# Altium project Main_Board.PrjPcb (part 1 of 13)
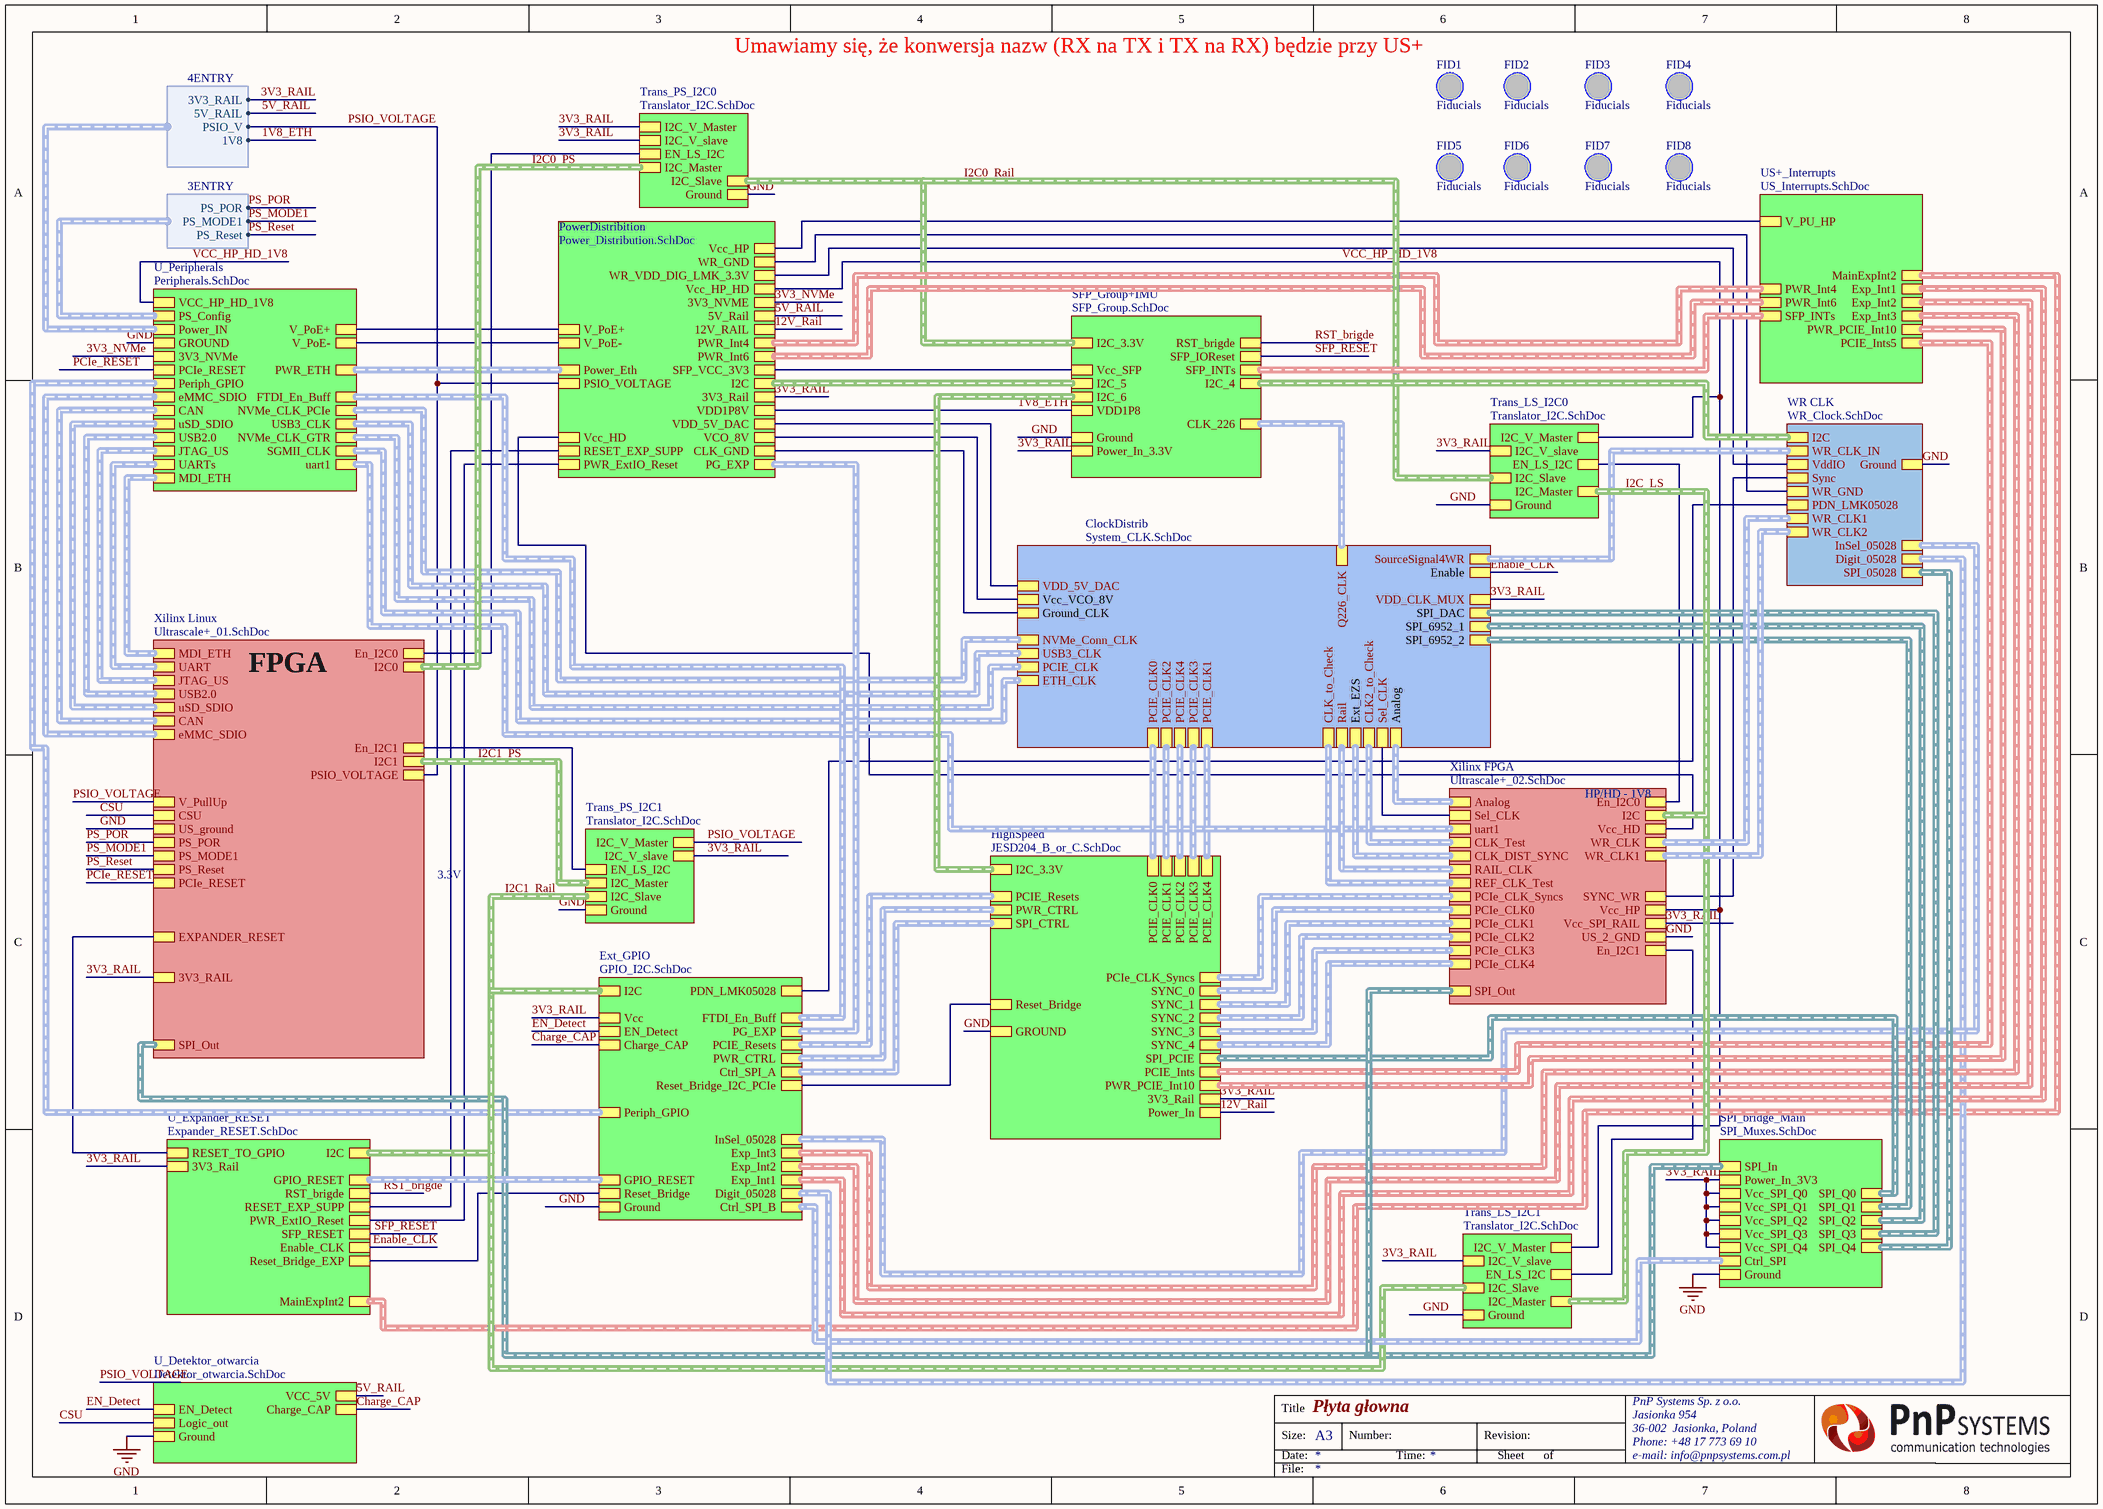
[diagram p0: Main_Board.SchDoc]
Address10: Jasionka 954; Address20: 36-002  Jasionka, Poland; Address30: Phone: +48 17 773 69 10; Address40: e-mail: info@pnpsystems.com.pl; CompanyName1: PnP Systems Sp. z o.o.
70 sheets, 2644 parts. Net scope: hierarchical (ports join the sheet entries above them; power ports are global).
Board file: MainBoardPCB.PcbDoc
Sheets:
  Main_Board.SchDoc
    Xilinx Linux = Ultrascale+_01.SchDoc
      PS_Config = PS_Config.SchDoc
      U_LED_US_1 = LED_US_1.SchDoc
    WR CLK = WR_Clock.SchDoc
    ClockDistrib = System_CLK.SchDoc
      DAC = DAC.SchDoc
      CLK_MUX = CLK_Mux.SchDoc
      LTC6952_1 = LTC6952_1.SchDoc
      LTC6952_0 = LTC6952.SchDoc
    Xilinx FPGA = Ultrascale+_02.SchDoc
    HighSpeed = JESD204_B_or_C.SchDoc
      PCIE0 = PCIe.SchDoc
      PCIE1 = PCIe.SchDoc
      PCIE2 = PCIe.SchDoc
      PCIE3 = PCIe.SchDoc
      PCIE4 = PCIe.SchDoc
      Bank 224 = Bank224.SchDoc
      Bank 225 = Bank225.SchDoc
      Bank 223 = Bank223.SchDoc
      I2C_Bridge_PCIE = I2C_Bridge.SchDoc
      SPI_bridge_PCIe = SPI_Muxes.SchDoc
      Power4HighSpeed = Power4HiSpeed.SchDoc
        U_Pomiar_pradu_napiecia_PCIe0 = Pomiar_pradu_napiecia.SchDoc
        U_Pomiar_pradu_napiecia_PCIe1 = Pomiar_pradu_napiecia.SchDoc
        U_Pomiar_pradu_napiecia_PCIe2 = Pomiar_pradu_napiecia.SchDoc
        U_Pomiar_pradu_napiecia_PCIe3 = Pomiar_pradu_napiecia.SchDoc
        U_Pomiar_pradu_napiecia_PCIe4 = Pomiar_pradu_napiecia.SchDoc
    PowerDistribition = Power_Distribution.SchDoc
      PowerSelector = Power_Switch.SchDoc
      HiCurrent = Power_Hi_Curr.SchDoc
        U_HI_Curr_ADP1850_1 = HI_Curr_ADP1850.SchDoc
        U_HI_Curr_ADP1850_3 = Power_ADP1850_Dual.SchDoc
        U_Power_ADP1850_Dual_2 = Power_ADP1850_Dual_1.SchDoc
        U_Pomiar_pradu_napiecia_3 = Pomiar_pradu_napiecia.SchDoc
        U_Pomiar_pradu_napiecia_4 = Pomiar_pradu_napiecia.SchDoc
        U_Pomiar_pradu_napiecia_5 = Pomiar_pradu_napiecia.SchDoc
        U_Pomiar_pradu_napiecia_6 = Pomiar_pradu_napiecia.SchDoc
        U_Pomiar_napiecia_high_curr = Pomiar_napiecia_high_curr.SchDoc
      LowCurr = Power_Low_Curr.SchDoc
      Zasilanie CLK = Zasilanie_CLKDistribution.SchDoc
        U_ADP1741_3 = ADP1741_3.6V_3.3V@2A.SchDoc
        5to3V3_1 = 5V_to_3V3.SchDoc
        5to3V3_2 = 5V_to_3V3.SchDoc
        U_LT3042_12V_5V_LNLDO = LT3042_12V_5V_LNLDO.SchDoc
        U_TPS7A88_5V_Dual_3 = TPS7A88_5V_Dual_3.3V_3.3V.SchDoc
        I2C_Expander_PWR_CLK = I2C_Expander.SchDoc
      Ram_Power = RAM_Power.SchDoc
      XilinxPower = XilinxPower.SchDoc
        U_FPGA_Decoupling = FPGA_Decoupling.SchDoc
      Ram = RAM.SchDoc
      GND = Ground.SchDoc
      U_Power_Ethernet = Power_Ethernet.SchDoc
      I2C_Expander_PWR_Dist = I2C_Expander.SchDoc
      U_Pomiar_pradu_napiecia_1 = Pomiar_pradu_napiecia.SchDoc
      U_Pomiar_pradu_napiecia_2 = Pomiar_pradu_napiecia.SchDoc
      U_Power_48_20V@3A = Power_48_20V@3A.SchDoc
      U_UM78M_12_8V = UM78M_12_8V.SchDoc
      U_TPS7A88_3V3_1V8_0V9V@2x1A = TPS7A88_3V3_1V8_0V9V@2x1A.SchDoc
      U_ADP1741_3V3_0V85 = ADP1741_3V3_0V85.SchDoc
      U_ST1L08_5V_0V6 = ST1L08_5V_0V6.SchDoc
      U_Power_LED = Power_LED.SchDoc
    Trans_LS_I2C0 = Translator_I2C.SchDoc
    Ext_GPIO = GPIO_I2C.SchDoc
      I2C_Bridge_GPIO = I2C_Bridge.SchDoc
      Ext_GPIO_Bank0 = Ext_GPIO_Bank0.SchDoc
        I2C_Expander_00 = I2C_Expander.SchDoc
        I2C_Expander_01 = I2C_Expander.SchDoc
        I2C_Expander_02 = I2C_Expander.SchDoc
      Ext_GPIO_Bank1 = Ext_GPIO_Bank1.SchDoc
        I2C_Expander_10 = I2C_Expander.SchDoc
        I2C_Expander_11 = I2C_Expander.SchDoc
        I2C_Expander_12 = I2C_Expander.SchDoc
      Ext_GPIO_Bank2 = Ext_GPIO_Bank2.SchDoc
    SFP_Group+IMU = SFP_Group.SchDoc
      SFP0 = SFP.SchDoc
      SFP1 = SFP1.SchDoc
      SFP2 = SFP2.SchDoc
      SFP3 = SFP3.SchDoc
      I2C_Bridge_SFP = I2C_Bridge.SchDoc
      Bank 226 = bank226.SchDoc
      IMU = IMU.SchDoc
      I2C_Expander_SFP = I2C_Expander.SchDoc
    Trans_PS_I2C0 = Translator_I2C.SchDoc
    Trans_PS_I2C1 = Translator_I2C.SchDoc
    SPI_bridge_Main = SPI_Muxes.SchDoc
    Trans_LS_I2C1 = Translator_I2C.SchDoc
    U_Detektor_otwarcia = Detektor_otwarcia.SchDoc
    U_Peripherals = Peripherals.SchDoc
      Gigabit Eth = RJ45.SchDoc
      NVMe = Sata.SchDoc
      µSD = uSD.SchDoc
      Debug = FTDI.SchDoc
        5V_to_3V3_for_FTDI = 5V_to_3V3.SchDoc
      USB3.0 = USB3.SchDoc
      U_CAN = CAN.SchDoc
      Flash_Memory = eMMC.SchDoc
      GTR = GTR.SchDoc
    U_Expander_RESET = Expander_RESET.SchDoc
      I2C_Expander_Main_Rst = I2C_Expander.SchDoc
    US+_Interrupts = US_Interrupts.SchDoc

## Sheet Main_Board.SchDoc: Płyta głowna
size A3; Organization: Altium Limited; Address1: L3, 12a Rodborough Rd; Address2: Frenchs Forest; Address3: NSW; Address4: Australia 2086

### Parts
FID1  Fiducials  [Fiducials]
FID2  Fiducials  [Fiducials]
FID3  Fiducials  [Fiducials]
FID4  Fiducials  [Fiducials]
FID5  Fiducials  [Fiducials]
FID6  Fiducials  [Fiducials]
FID7  Fiducials  [Fiducials]
FID8  Fiducials  [Fiducials]

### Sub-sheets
ClockDistrib = System_CLK.SchDoc: SPI_6952_1 (harness SPI_H), Ground_CLK, Ext_EZS (harness Diff_1Pair), Enable, Analog (harness Analog), Vcc_VCO_8V, SPI_6952_2 (harness SPI_H), SPI_DAC (harness SPI_H), Q226_CLK (harness Diff_1Pair), SourceSignal4WR (harness Diff_1Pair), Rail (harness Diff_1Pair), CLK_to_Check (harness Diff_1Pair), ETH_CLK (harness Diff_1Pair), USB3_CLK (harness Diff_1Pair), PCIE_CLK (harness Diff_1Pair), Sel_CLK, CLK2_to_Check (harness Diff_1Pair), NVMe_Conn_CLK (harness Diff_1Pair), VDD_5V_DAC, VDD_CLK_MUX, PCIE_CLK0 (harness Diff_1Pair), PCIE_CLK2 (harness Diff_1Pair), PCIE_CLK4 (harness Diff_1Pair), PCIE_CLK3 (harness Diff_1Pair), PCIE_CLK1 (harness Diff_1Pair)
Ext_GPIO = GPIO_I2C.SchDoc: Ctrl_SPI_B (harness Ctrl_SPI_PCIE), Ctrl_SPI_A (harness Ctrl_SPI_PCIE), Ground, Vcc, I2C (harness I2C), Digit_05028 (harness 05028_Digit), GPIO_RESET (harness Exp_Reset3), Reset_Bridge, PG_EXP (harness 7_PG), PDN_LMK05028, EN_Detect, Charge_CAP, Exp_Int1 (harness Exp_Int), PCIE_Resets (harness PCIe_Resets), PWR_CTRL (harness Ctrl_Pwr4HiSpeed), Periph_GPIO (harness Periph_GPIO), Exp_Int2 (harness Exp_Int), Exp_Int3 (harness Exp_Int), InSel_05028 (harness InSel_05028), FTDI_En_Buff (harness FTDI_En_Buff), Reset_Bridge_I2C_PCIe
HighSpeed = JESD204_B_or_C.SchDoc: PCIE_Resets (harness PCIe_Resets), SPI_PCIE (harness SPI_H), Power_In, SPI_CTRL (harness Ctrl_SPI_PCIE), PWR_CTRL (harness Ctrl_Pwr4HiSpeed), I2C_3.3V (harness I2C), Reset_Bridge, 3V3_Rail, PWR_PCIE_Int10 (harness PWR_PCIE_Int10), GROUND, PCIE_Ints (harness PCIe_Ints), PCIe_CLK_Syncs (harness PCIe_CLK_Syncs), SYNC_4 (harness Diff_3Diff_Pcie), SYNC_3 (harness Diff_3Diff_Pcie), SYNC_2 (harness Diff_3Diff_Pcie), SYNC_1 (harness Diff_3Diff_Pcie), SYNC_0 (harness Diff_3Diff_Pcie), PCIE_CLK4 (harness Diff_1Pair), PCIE_CLK0 (harness Diff_1Pair), PCIE_CLK3 (harness Diff_1Pair), PCIE_CLK1 (harness Diff_1Pair), PCIE_CLK2 (harness Diff_1Pair)
PowerDistribition = Power_Distribution.SchDoc: Power_Eth (harness Power_ETH), V_PoE-, V_PoE+, SFP_VCC_3V3, 3V3_Rail, I2C (harness I2C), VDD1P8V, 12V_RAIL, PWR_Int4 (harness PWR_Int4), PWR_ExtIO_Reset, 5V_Rail, PWR_Int6 (harness PWR_Interrupt), WR_VDD_DIG_LMK_3.3V, PSIO_VOLTAGE, VCO_8V, 3V3_NVME, VDD_5V_DAC, Vcc_HP_HD, WR_GND, CLK_GND, RESET_EXP_SUPP, PG_EXP (harness 7_PG), Vcc_HP, Vcc_HD
SFP_Group+IMU = SFP_Group.SchDoc: I2C_3.3V (harness I2C), RST_brigde, Ground, Vcc_SFP, SFP_INTs (harness SFP_INTs), I2C_5 (harness I2C), Power_In_3.3V, VDD1P8, SFP_IOReset, CLK_226 (harness Diff_1Pair), I2C_6 (harness I2C), I2C_4 (harness I2C)
SPI_bridge_Main = SPI_Muxes.SchDoc: SPI_Q0 (harness SPI_H), SPI_Q1 (harness SPI_H), SPI_Q2 (harness SPI_H), SPI_Q3 (harness SPI_H), SPI_Q4 (harness SPI_H), SPI_In (harness SPI_H), Power_In_3V3, Ctrl_SPI (harness Ctrl_SPI_PCIE), Vcc_SPI_Q4, Vcc_SPI_Q3, Vcc_SPI_Q2, Vcc_SPI_Q1, Vcc_SPI_Q0, Ground
Trans_LS_I2C0 = Translator_I2C.SchDoc: Ground, EN_LS_I2C, I2C_Slave (harness I2C), I2C_Master (harness I2C), I2C_V_slave, I2C_V_Master
Trans_LS_I2C1 = Translator_I2C.SchDoc: Ground, EN_LS_I2C, I2C_Slave (harness I2C), I2C_Master (harness I2C), I2C_V_slave, I2C_V_Master
Trans_PS_I2C0 = Translator_I2C.SchDoc: Ground, EN_LS_I2C, I2C_Slave (harness I2C), I2C_Master (harness I2C), I2C_V_slave, I2C_V_Master
Trans_PS_I2C1 = Translator_I2C.SchDoc: Ground, EN_LS_I2C, I2C_Slave (harness I2C), I2C_Master (harness I2C), I2C_V_slave, I2C_V_Master
U_Detektor_otwarcia = Detektor_otwarcia.SchDoc: EN_Detect, Logic_out, Ground, VCC_5V, Charge_CAP
U_Expander_RESET = Expander_RESET.SchDoc: 3V3_Rail, RESET_TO_GPIO, GPIO_RESET (harness Exp_Reset3), RESET_EXP_SUPP, PWR_ExtIO_Reset, SFP_RESET, MainExpInt2 (harness MainExpInt2), RST_brigde, Enable_CLK, Reset_Bridge_EXP, I2C (harness I2C)
U_Peripherals = Peripherals.SchDoc: 3V3_NVMe, GROUND, V_PoE+, V_PoE-, PS_Config (harness 3ENTRY), Periph_GPIO (harness Periph_GPIO), Power_IN (harness 4ENTRY), PWR_ETH (harness Power_ETH), uart1 (harness uart), UARTs (harness 2Uarts), USB2.0 (harness USB_H), MDI_ETH (harness MDI_ETH), CAN (harness CAN), uSD_SDIO (harness SDIO_H), eMMC_SDIO (harness SDIO_H), NVMe_CLK_GTR (harness Diff_1Pair), USB3_CLK (harness Diff_1Pair), SGMII_CLK (harness Diff_1Pair), JTAG_US (harness JTAG), NVMe_CLK_PCIe (harness Diff_1Pair), VCC_HP_HD_1V8, FTDI_En_Buff (harness FTDI_En_Buff), PCIe_RESET
US+_Interrupts = US_Interrupts.SchDoc: V_PU_HP, MainExpInt2 (harness MainExpInt2), PCIE_Ints5 (harness PCIe_Ints5), PWR_Int4 (harness PWR_Int4), PWR_Int6 (harness PWR_Interrupt), SFP_INTs (harness SFP_INTs), Exp_Int1 (harness Exp_Int), PWR_PCIE_Int10 (harness PWR_PCIE_Int10), Exp_Int2 (harness Exp_Int), Exp_Int3 (harness Exp_Int)
WR CLK = WR_Clock.SchDoc: WR_CLK1 (harness Diff_1Pair), WR_CLK2 (harness Diff_1Pair), Sync, VddIO, WR_CLK_IN (harness Diff_1Pair), SPI_05028 (harness SPI_H), Ground, Digit_05028 (harness 05028_Digit), I2C (harness I2C), WR_GND, PDN_LMK05028, InSel_05028 (harness InSel_05028)
Xilinx FPGA = Ultrascale+_02.SchDoc: I2C (harness I2C), SPI_Out (harness SPI_H), uart1 (harness uart), En_I2C0, WR_CLK (harness Diff_1Pair), REF_CLK_Test (harness Diff_1Pair), RAIL_CLK (harness Diff_1Pair), Analog (harness Analog), CLK_DIST_SYNC (harness Diff_1Pair), WR_CLK1 (harness Diff_1Pair), Vcc_HP, US_2_GND, Vcc_SPI_RAIL, En_I2C1, Sel_CLK, SYNC_WR, CLK_Test (harness Diff_1Pair), PCIe_CLK_Syncs (harness PCIe_CLK_Syncs), Vcc_HD, PCIe_CLK2 (harness Diff_3Diff_Pcie), PCIe_CLK4 (harness Diff_3Diff_Pcie), PCIe_CLK1 (harness Diff_3Diff_Pcie), PCIe_CLK3 (harness Diff_3Diff_Pcie), PCIe_CLK0 (harness Diff_3Diff_Pcie)
Xilinx Linux = Ultrascale+_01.SchDoc: I2C0 (harness I2C), SPI_Out (harness SPI_H), I2C1 (harness I2C), En_I2C0, En_I2C1, V_PullUp, US_ground, CSU, PSIO_VOLTAGE, PS_POR, PS_MODE1, PS_Reset, UART (harness 2Uarts), EXPANDER_RESET, MDI_ETH (harness MDI_ETH), USB2.0 (harness USB_H), eMMC_SDIO (harness SDIO_H), CAN (harness CAN), uSD_SDIO (harness SDIO_H), JTAG_US (harness JTAG), PCIe_RESET, 3V3_RAIL  | Parameter 1: FPGA

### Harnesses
4ENTRY: 3V3_RAIL, 5V_RAIL, PSIO_V, 1V8
3ENTRY: PS_POR, PS_MODE1, PS_Reset

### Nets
GND: sheet Xilinx Linux/US_ground, sheet WR CLK/Ground, sheet Xilinx FPGA/US_2_GND, sheet HighSpeed/GROUND, sheet Trans_LS_I2C0/Ground, sheet Ext_GPIO/Ground, sheet SFP_Group+IMU/Ground, sheet Trans_PS_I2C0/Ground, sheet Trans_PS_I2C1/Ground, sheet SPI_bridge_Main/Ground, sheet Trans_LS_I2C1/Ground, sheet U_Detektor_otwarcia/Ground, sheet U_Peripherals/GROUND  [project net B503_Ground]
1V8_ETH: sheet PowerDistribition/VDD1P8V, sheet SFP_Group+IMU/VDD1P8, sheet U_Peripherals/Power_IN.1V8  [project net 1V8@1.5A]
3V3_NVMe: sheet PowerDistribition/3V3_NVME, sheet U_Peripherals/3V3_NVMe
3V3_RAIL: sheet Xilinx Linux/3V3_RAIL, sheet ClockDistrib/VDD_CLK_MUX, sheet Xilinx FPGA/Vcc_SPI_RAIL, sheet HighSpeed/3V3_Rail, sheet PowerDistribition/SFP_VCC_3V3, sheet PowerDistribition/3V3_Rail, sheet Trans_LS_I2C0/I2C_V_slave, sheet Ext_GPIO/Vcc, sheet SFP_Group+IMU/Vcc_SFP, sheet SFP_Group+IMU/Power_In_3.3V, sheet Trans_PS_I2C0/I2C_V_slave, sheet Trans_PS_I2C0/I2C_V_Master, sheet Trans_PS_I2C1/I2C_V_slave, sheet SPI_bridge_Main/Power_In_3V3, sheet SPI_bridge_Main/Vcc_SPI_Q4, sheet SPI_bridge_Main/Vcc_SPI_Q3, sheet SPI_bridge_Main/Vcc_SPI_Q2, sheet SPI_bridge_Main/Vcc_SPI_Q1, sheet SPI_bridge_Main/Vcc_SPI_Q0, sheet Trans_LS_I2C1/I2C_V_slave, sheet U_Expander_RESET/3V3_Rail, sheet U_Peripherals/Power_IN.3V3_RAIL
5V_LN: sheet ClockDistrib/VDD_5V_DAC, sheet PowerDistribition/VDD_5V_DAC
5V_RAIL: sheet PowerDistribition/5V_Rail, sheet U_Detektor_otwarcia/VCC_5V, sheet U_Peripherals/Power_IN.5V_RAIL
12V_Rail: sheet HighSpeed/Power_In, sheet PowerDistribition/12V_RAIL  [project net 12V_LT3042]
AGND: sheet ClockDistrib/Ground_CLK, sheet PowerDistribition/CLK_GND
Charge_CAP: sheet Ext_GPIO/Charge_CAP, sheet U_Detektor_otwarcia/Charge_CAP
CSU: sheet Xilinx Linux/CSU, sheet U_Detektor_otwarcia/Logic_out
D_05028_G0: sheet WR CLK/Sync, sheet Xilinx FPGA/SYNC_WR
EN_Detect: sheet Ext_GPIO/EN_Detect, sheet U_Detektor_otwarcia/EN_Detect
Enable_CLK: sheet ClockDistrib/Enable, sheet U_Expander_RESET/Enable_CLK
EXPANDER_RESET: sheet Xilinx Linux/EXPANDER_RESET, sheet U_Expander_RESET/RESET_TO_GPIO
GPIOa_11.GPIO7: sheet WR CLK/PDN_LMK05028, sheet Ext_GPIO/PDN_LMK05028
GPIOb_02.GPIO0: sheet HighSpeed/Reset_Bridge, sheet Ext_GPIO/Reset_Bridge_I2C_PCIe
Ground: sheet WR CLK/WR_GND, sheet PowerDistribition/WR_GND
MIO_GPIO_2_74: sheet Xilinx Linux/En_I2C1, sheet Trans_PS_I2C1/EN_LS_I2C
MIO_GPIO_2_75: sheet Xilinx Linux/En_I2C0, sheet Trans_PS_I2C0/EN_LS_I2C
PCIe_RESET: sheet Xilinx Linux/PCIe_RESET, sheet U_Peripherals/PCIe_RESET
PGND: sheet PowerDistribition/V_PoE-, sheet U_Peripherals/V_PoE-
PS_MODE1: sheet Xilinx Linux/PS_MODE1, sheet U_Peripherals/PS_Config.PS_MODE1
PS_POR: sheet Xilinx Linux/PS_POR, sheet U_Peripherals/PS_Config.PS_POR
PS_Reset: sheet Xilinx Linux/PS_Reset, sheet U_Peripherals/PS_Config.PS_Reset
PSIO_VOLTAGE: sheet Xilinx Linux/V_PullUp, sheet Xilinx Linux/PSIO_VOLTAGE, sheet PowerDistribition/PSIO_VOLTAGE, sheet Trans_PS_I2C1/I2C_V_Master, sheet U_Peripherals/Power_IN.PSIO_V  [project net ETH_VDDIO]
PWR_ExtIO_nReset: sheet PowerDistribition/PWR_ExtIO_Reset, sheet U_Expander_RESET/PWR_ExtIO_Reset
RST_brigde: sheet SFP_Group+IMU/RST_brigde, sheet U_Expander_RESET/RST_brigde
SetClk_Si53323_2: sheet ClockDistrib/Sel_CLK, sheet Xilinx FPGA/Sel_CLK
SFP_RESET: sheet SFP_Group+IMU/SFP_IOReset, sheet U_Expander_RESET/SFP_RESET  [project net SFP_IO_nReset]
V_PoE+: sheet PowerDistribition/V_PoE+, sheet U_Peripherals/V_PoE+
VCC_HP_HD_1V8: sheet Xilinx FPGA/Vcc_HP, sheet Xilinx FPGA/Vcc_HD, sheet PowerDistribition/Vcc_HP_HD, sheet PowerDistribition/Vcc_HP, sheet PowerDistribition/Vcc_HD, sheet Trans_LS_I2C0/I2C_V_Master, sheet Trans_LS_I2C1/I2C_V_Master, sheet U_Peripherals/VCC_HP_HD_1V8, sheet US+_Interrupts/V_PU_HP  [project net US+_MGTVccAux]
VDD_DIG: sheet WR CLK/VddIO, sheet PowerDistribition/WR_VDD_DIG_LMK_3.3V
NetC713_2: sheet ClockDistrib/Vcc_VCO_8V, sheet PowerDistribition/VCO_8V
NetR754_1: sheet PowerDistribition/RESET_EXP_SUPP, sheet U_Expander_RESET/RESET_EXP_SUPP
NetR918_2: sheet Xilinx FPGA/En_I2C0, sheet Trans_LS_I2C0/EN_LS_I2C
NetR919_2: sheet Xilinx FPGA/En_I2C1, sheet Trans_LS_I2C1/EN_LS_I2C
NetSP12_I2C_Bridge_GPIO_1: sheet Ext_GPIO/Reset_Bridge, sheet U_Expander_RESET/Reset_Bridge_EXP

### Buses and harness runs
harness I2C0_PS = sheet Trans_PS_I2C0/I2C_Master = sheet Xilinx Linux/I2C0
harness I2C0_Rail = sheet SFP_Group+IMU/I2C_3.3V = sheet Trans_LS_I2C0/I2C_Slave = sheet Trans_PS_I2C0/I2C_Slave
harness I2C1_PS = sheet Trans_PS_I2C1/I2C_Master = sheet Xilinx Linux/I2C1
harness I2C1_Rail = sheet Ext_GPIO/I2C = sheet Trans_LS_I2C1/I2C_Slave = sheet Trans_PS_I2C1/I2C_Slave = sheet U_Expander_RESET/I2C
harness I2C_LS = sheet Trans_LS_I2C0/I2C_Master = sheet Trans_LS_I2C1/I2C_Master = sheet Xilinx FPGA/I2C
harness sheet ClockDistrib/Analog = sheet Xilinx FPGA/Analog
harness sheet ClockDistrib/CLK2_to_Check = sheet Xilinx FPGA/CLK_Test
harness sheet ClockDistrib/CLK_to_Check = sheet Xilinx FPGA/REF_CLK_Test
harness sheet ClockDistrib/ETH_CLK = sheet U_Peripherals/SGMII_CLK
harness sheet ClockDistrib/Ext_EZS = sheet Xilinx FPGA/CLK_DIST_SYNC
harness sheet ClockDistrib/NVMe_Conn_CLK = sheet U_Peripherals/NVMe_CLK_PCIe
harness sheet ClockDistrib/PCIE_CLK0 = sheet HighSpeed/PCIE_CLK0
harness sheet ClockDistrib/PCIE_CLK1 = sheet HighSpeed/PCIE_CLK4
harness sheet ClockDistrib/PCIE_CLK2 = sheet HighSpeed/PCIE_CLK1
harness sheet ClockDistrib/PCIE_CLK3 = sheet HighSpeed/PCIE_CLK3
harness sheet ClockDistrib/PCIE_CLK4 = sheet HighSpeed/PCIE_CLK2
harness sheet ClockDistrib/PCIE_CLK = sheet U_Peripherals/NVMe_CLK_GTR
harness sheet ClockDistrib/Q226_CLK = sheet SFP_Group+IMU/CLK_226
harness sheet ClockDistrib/Rail = sheet Xilinx FPGA/RAIL_CLK
harness sheet ClockDistrib/SourceSignal4WR = sheet WR CLK/WR_CLK_IN
harness sheet ClockDistrib/SPI_6952_1 = sheet SPI_bridge_Main/SPI_Q2
harness sheet ClockDistrib/SPI_6952_2 = sheet SPI_bridge_Main/SPI_Q1
harness sheet ClockDistrib/SPI_DAC = sheet SPI_bridge_Main/SPI_Q3
harness sheet ClockDistrib/USB3_CLK = sheet U_Peripherals/USB3_CLK
harness sheet Ext_GPIO/Ctrl_SPI_A = sheet HighSpeed/SPI_CTRL
harness sheet Ext_GPIO/Ctrl_SPI_B = sheet SPI_bridge_Main/Ctrl_SPI
harness sheet Ext_GPIO/Digit_05028 = sheet WR CLK/Digit_05028
harness sheet Ext_GPIO/Exp_Int1 = sheet US+_Interrupts/Exp_Int1
harness sheet Ext_GPIO/Exp_Int2 = sheet US+_Interrupts/Exp_Int2
harness sheet Ext_GPIO/Exp_Int3 = sheet US+_Interrupts/Exp_Int3
harness sheet Ext_GPIO/FTDI_En_Buff = sheet U_Peripherals/FTDI_En_Buff
harness sheet Ext_GPIO/GPIO_RESET = sheet U_Expander_RESET/GPIO_RESET
harness sheet Ext_GPIO/InSel_05028 = sheet WR CLK/InSel_05028
harness sheet Ext_GPIO/PCIE_Resets = sheet HighSpeed/PCIE_Resets
harness sheet Ext_GPIO/Periph_GPIO = sheet U_Peripherals/Periph_GPIO
harness sheet Ext_GPIO/PG_EXP = sheet PowerDistribition/PG_EXP
harness sheet Ext_GPIO/PWR_CTRL = sheet HighSpeed/PWR_CTRL
harness sheet HighSpeed/I2C_3.3V = sheet SFP_Group+IMU/I2C_6
harness sheet HighSpeed/PCIe_CLK_Syncs = sheet Xilinx FPGA/PCIe_CLK_Syncs
harness sheet HighSpeed/PCIE_Ints = sheet US+_Interrupts/PCIE_Ints5
harness sheet HighSpeed/PWR_PCIE_Int10 = sheet US+_Interrupts/PWR_PCIE_Int10
harness sheet HighSpeed/SPI_PCIE = sheet SPI_bridge_Main/SPI_Q0
harness sheet HighSpeed/SYNC_0 = sheet Xilinx FPGA/PCIe_CLK0
harness sheet HighSpeed/SYNC_1 = sheet Xilinx FPGA/PCIe_CLK1
harness sheet HighSpeed/SYNC_2 = sheet Xilinx FPGA/PCIe_CLK2
harness sheet HighSpeed/SYNC_3 = sheet Xilinx FPGA/PCIe_CLK3
harness sheet HighSpeed/SYNC_4 = sheet Xilinx FPGA/PCIe_CLK4
harness sheet PowerDistribition/I2C = sheet SFP_Group+IMU/I2C_5
harness sheet PowerDistribition/Power_Eth = sheet U_Peripherals/PWR_ETH
harness sheet PowerDistribition/PWR_Int4 = sheet US+_Interrupts/PWR_Int4
harness sheet PowerDistribition/PWR_Int6 = sheet US+_Interrupts/PWR_Int6
harness sheet SFP_Group+IMU/I2C_4 = sheet WR CLK/I2C
harness sheet SFP_Group+IMU/SFP_INTs = sheet US+_Interrupts/SFP_INTs
harness sheet SPI_bridge_Main/SPI_In = sheet Xilinx FPGA/SPI_Out = sheet Xilinx Linux/SPI_Out
harness sheet SPI_bridge_Main/SPI_Q4 = sheet WR CLK/SPI_05028
harness sheet U_Expander_RESET/MainExpInt2 = sheet US+_Interrupts/MainExpInt2
harness sheet U_Peripherals/CAN = sheet Xilinx Linux/CAN
harness sheet U_Peripherals/eMMC_SDIO = sheet Xilinx Linux/eMMC_SDIO
harness sheet U_Peripherals/JTAG_US = sheet Xilinx Linux/JTAG_US
harness sheet U_Peripherals/MDI_ETH = sheet Xilinx Linux/MDI_ETH
harness sheet U_Peripherals/uart1 = sheet Xilinx FPGA/uart1
harness sheet U_Peripherals/UARTs = sheet Xilinx Linux/UART
harness sheet U_Peripherals/USB2.0 = sheet Xilinx Linux/USB2.0
harness sheet U_Peripherals/uSD_SDIO = sheet Xilinx Linux/uSD_SDIO
harness sheet WR CLK/WR_CLK1 = sheet Xilinx FPGA/WR_CLK
harness sheet WR CLK/WR_CLK2 = sheet Xilinx FPGA/WR_CLK1

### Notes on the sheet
- Umawiamy się, że konwersja nazw (RX na TX i TX na RX) będzie przy US+
- HP/HD - 1V8
- 3.3V

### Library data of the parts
FID1-FID8 = Fid

## Sheet Ultrascale+_01.SchDoc: Ultrascale+_01
size A3; Organization: Altium Limited; Address1: L3, 12a Rodborough Rd; Address2: Frenchs Forest; Address3: NSW; Address4: Australia 2086
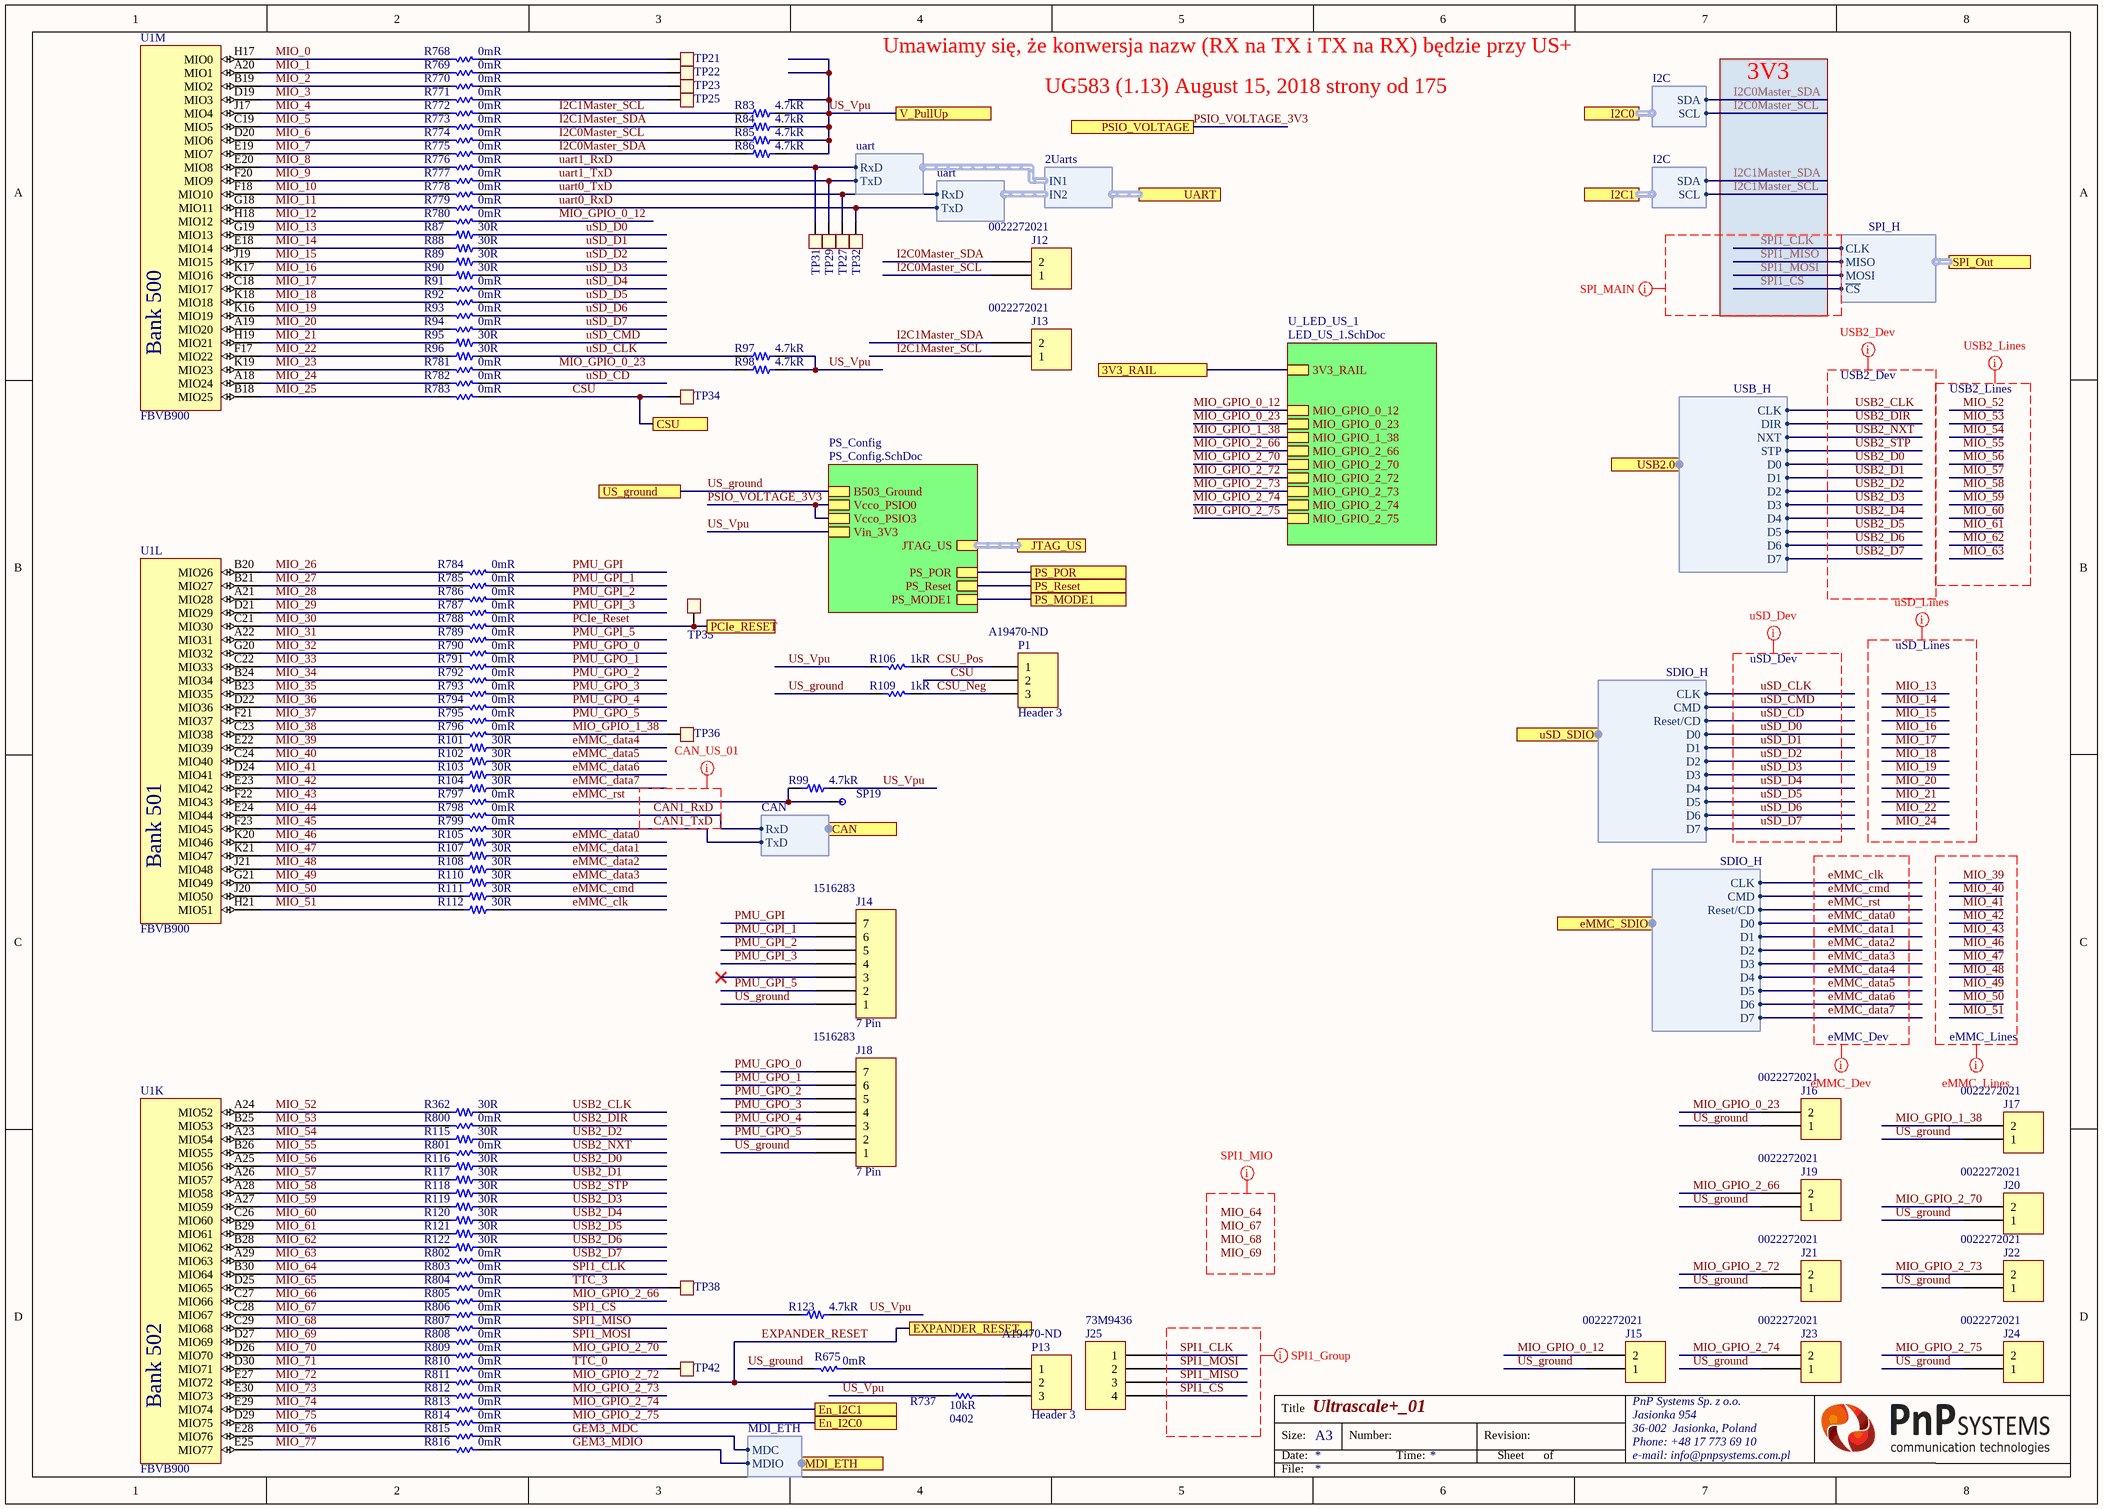
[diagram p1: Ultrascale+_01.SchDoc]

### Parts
J12  Supplier Part Number 1: 0022272021  [MOLEX KK 0022272021]  (hidden comment: MOLEX - 22-27-2021 - WIRE-BOARD CONNECTOR HEADER 2 POSITION, 2.54MM)
J13  Supplier Part Number 1: 0022272021  [MOLEX KK 0022272021]  (hidden comment: MOLEX - 22-27-2021 - WIRE-BOARD CONNECTOR HEADER 2 POSITION, 2.54MM)
J14  7 Pin  Supplier Part Number 1: 1516283  [JST XH B7B-XH-A]
J15  Supplier Part Number 1: 0022272021  [MOLEX KK 0022272021]  (hidden comment: MOLEX - 22-27-2021 - WIRE-BOARD CONNECTOR HEADER 2 POSITION, 2.54MM)
J16  Supplier Part Number 1: 0022272021  [MOLEX KK 0022272021]  (hidden comment: MOLEX - 22-27-2021 - WIRE-BOARD CONNECTOR HEADER 2 POSITION, 2.54MM)
J17  Supplier Part Number 1: 0022272021  [MOLEX KK 0022272021]  (hidden comment: MOLEX - 22-27-2021 - WIRE-BOARD CONNECTOR HEADER 2 POSITION, 2.54MM)
J18  7 Pin  Supplier Part Number 1: 1516283  [JST XH B7B-XH-A]
J19  Supplier Part Number 1: 0022272021  [MOLEX KK 0022272021]  (hidden comment: MOLEX - 22-27-2021 - WIRE-BOARD CONNECTOR HEADER 2 POSITION, 2.54MM)
J20  Supplier Part Number 1: 0022272021  [MOLEX KK 0022272021]  (hidden comment: MOLEX - 22-27-2021 - WIRE-BOARD CONNECTOR HEADER 2 POSITION, 2.54MM)
J21  Supplier Part Number 1: 0022272021  [MOLEX KK 0022272021]  (hidden comment: MOLEX - 22-27-2021 - WIRE-BOARD CONNECTOR HEADER 2 POSITION, 2.54MM)
J22  Supplier Part Number 1: 0022272021  [MOLEX KK 0022272021]  (hidden comment: MOLEX - 22-27-2021 - WIRE-BOARD CONNECTOR HEADER 2 POSITION, 2.54MM)
J23  Supplier Part Number 1: 0022272021  [MOLEX KK 0022272021]  (hidden comment: MOLEX - 22-27-2021 - WIRE-BOARD CONNECTOR HEADER 2 POSITION, 2.54MM)
J24  Supplier Part Number 1: 0022272021  [MOLEX KK 0022272021]  (hidden comment: MOLEX - 22-27-2021 - WIRE-BOARD CONNECTOR HEADER 2 POSITION, 2.54MM)
J25  Supplier Part Number 1: 73M9436  [JST XH B4B-XH-A]  (hidden comment: JST (JAPAN SOLDERLESS TERMINALS) - B4B-XH-A (LF)(SN) - Wire-To-Board-Steckverbinder, vertikal, 2.5 mm, 4 Kontakt(e), Stiftleiste, Baureihe XH)
P1  Header 3  Supplier Part Number 1: A19470-ND  [HDR1X3]
P13  Header 3  Supplier Part Number 1: A19470-ND  [HDR1X3]
R83  4.7kR  [RES 0402/1005 RF KK]
R84  4.7kR  [RES 0402/1005 RF KK]
R85  4.7kR  [RES 0402/1005 RF KK]
R86  4.7kR  [RES 0402/1005 RF KK]
R87  30R  [RES 0402/1005 RF KK]
R88  30R  [RES 0402/1005 RF KK]
R89  30R  [RES 0402/1005 RF KK]
R90  30R  [RES 0402/1005 RF KK]
R91  0mR  [RES 0402/1005 RF KK]
R92  0mR  [RES 0402/1005 RF KK]
R93  0mR  [RES 0402/1005 RF KK]
R94  0mR  [RES 0402/1005 RF KK]
R95  30R  [RES 0402/1005 RF KK]
R96  30R  [RES 0402/1005 RF KK]
R97  4.7kR  [RES 0402/1005 RF KK]
R98  4.7kR  [RES 0402/1005 RF KK]
R99  4.7kR  [RES 0402/1005 RF KK]
R101  30R  [RES 0402/1005 RF KK]
R102  30R  [RES 0402/1005 RF KK]
R103  30R  [RES 0402/1005 RF KK]
R104  30R  [RES 0402/1005 RF KK]
R105  30R  [RES 0402/1005 RF KK]
R106  1kR  [RES 0402/1005 RF KK]
R107  30R  [RES 0402/1005 RF KK]
R108  30R  [RES 0402/1005 RF KK]
R109  1kR  [RES 0402/1005 RF KK]
R110  30R  [RES 0402/1005 RF KK]
R111  30R  [RES 0402/1005 RF KK]
R112  30R  [RES 0402/1005 RF KK]
R115  30R  [RES 0402/1005 RF KK]
R116  30R  [RES 0402/1005 RF KK]
R117  30R  [RES 0402/1005 RF KK]
R118  30R  [RES 0402/1005 RF KK]
R119  30R  [RES 0402/1005 RF KK]
R120  30R  [RES 0402/1005 RF KK]
R121  30R  [RES 0402/1005 RF KK]
R122  30R  [RES 0402/1005 RF KK]
R123  4.7kR  [RES 0402/1005 RF KK]
R362  30R  [RES 0402/1005 RF KK]
R675  0mR  [RES 0402/1005 RF KK]
R737  10kR  Case Code (Imperial): 0402  [RES 0402/1005 RF KK]
R768  0mR  [RES 0402/1005 RF KK]
R769  0mR  [RES 0402/1005 RF KK]
R770  0mR  [RES 0402/1005 RF KK]
R771  0mR  [RES 0402/1005 RF KK]
R772  0mR  [RES 0402/1005 RF KK]
R773  0mR  [RES 0402/1005 RF KK]
R774  0mR  [RES 0402/1005 RF KK]
R775  0mR  [RES 0402/1005 RF KK]
R776  0mR  [RES 0402/1005 RF KK]
R777  0mR  [RES 0402/1005 RF KK]
R778  0mR  [RES 0402/1005 RF KK]
R779  0mR  [RES 0402/1005 RF KK]
R780  0mR  [RES 0402/1005 RF KK]
R781  0mR  [RES 0402/1005 RF KK]
R782  0mR  [RES 0402/1005 RF KK]
R783  0mR  [RES 0402/1005 RF KK]
R784  0mR  [RES 0402/1005 RF KK]
R785  0mR  [RES 0402/1005 RF KK]
R786  0mR  [RES 0402/1005 RF KK]
R787  0mR  [RES 0402/1005 RF KK]
R788  0mR  [RES 0402/1005 RF KK]
R789  0mR  [RES 0402/1005 RF KK]
R790  0mR  [RES 0402/1005 RF KK]
R791  0mR  [RES 0402/1005 RF KK]
R792  0mR  [RES 0402/1005 RF KK]
R793  0mR  [RES 0402/1005 RF KK]
R794  0mR  [RES 0402/1005 RF KK]
R795  0mR  [RES 0402/1005 RF KK]
R796  0mR  [RES 0402/1005 RF KK]
R797  0mR  [RES 0402/1005 RF KK]
R798  0mR  [RES 0402/1005 RF KK]
R799  0mR  [RES 0402/1005 RF KK]
R800  0mR  [RES 0402/1005 RF KK]
R801  0mR  [RES 0402/1005 RF KK]
R802  0mR  [RES 0402/1005 RF KK]
R803  0mR  [RES 0402/1005 RF KK]
R804  0mR  [RES 0402/1005 RF KK]
R805  0mR  [RES 0402/1005 RF KK]
R806  0mR  [RES 0402/1005 RF KK]
R807  0mR  [RES 0402/1005 RF KK]
R808  0mR  [RES 0402/1005 RF KK]
R809  0mR  [RES 0402/1005 RF KK]
R810  0mR  [RES 0402/1005 RF KK]
R811  0mR  [RES 0402/1005 RF KK]
R812  0mR  [RES 0402/1005 RF KK]
R813  0mR  [RES 0402/1005 RF KK]
R814  0mR  [RES 0402/1005 RF KK]
R815  0mR  [RES 0402/1005 RF KK]
R816  0mR  [RES 0402/1005 RF KK]
SP19  SP  [MeasureTP]  (value not drawn)
TP21  TestPoint  [TestPoint]  (value not drawn)
TP22  TestPoint  [TestPoint]  (value not drawn)
TP23  TestPoint  [TestPoint]  (value not drawn)
TP25  TestPoint  [TestPoint]  (value not drawn)
TP27  TestPoint  [TestPoint]  (value not drawn)
TP29  TestPoint  [TestPoint]  (value not drawn)
TP31  TestPoint  [TestPoint]  (value not drawn)
TP32  TestPoint  [TestPoint]  (value not drawn)
TP34  TestPoint  [TestPoint]  (value not drawn)
TP35  TestPoint  [TestPoint]  (value not drawn)
TP36  TestPoint  [TestPoint]  (value not drawn)
TP38  TestPoint  [TestPoint]  (value not drawn)
TP42  TestPoint  [TestPoint]  (value not drawn)
U1  FBVB900  [FBVB900 XX]  (parts K,L,M of 23)

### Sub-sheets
PS_Config = PS_Config.SchDoc: JTAG_US (harness JTAG), B503_Ground, Vcco_PSIO0, Vcco_PSIO3, Vin_3V3, PS_POR, PS_Reset, PS_MODE1
U_LED_US_1 = LED_US_1.SchDoc: 3V3_RAIL, MIO_GPIO_0_12, MIO_GPIO_0_23, MIO_GPIO_1_38, MIO_GPIO_2_66, MIO_GPIO_2_70, MIO_GPIO_2_72, MIO_GPIO_2_73, MIO_GPIO_2_74, MIO_GPIO_2_75

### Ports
3V3_RAIL, CAN (harness CAN), CSU, eMMC_SDIO (harness SDIO_H), En_I2C0, En_I2C1, EXPANDER_RESET, I2C0 (harness I2C), I2C1 (harness I2C), JTAG_US (harness JTAG), MDI_ETH (harness MDI_ETH), PCIe_RESET, PS_MODE1, PS_POR, PS_Reset, PSIO_VOLTAGE, SPI_Out (harness SPI_H), UART (harness 2Uarts), US_ground, USB2.0 (harness USB_H), uSD_SDIO (harness SDIO_H), V_PullUp

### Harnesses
I2C: SDA, SCL
SPI_H: CLK, MISO, MOSI, ~{CS}
SDIO_H: CLK, CMD, Reset/CD, D0, D1, D2, D3, D4, D5, D6, D7
uart: RxD, TxD
USB_H: CLK, DIR, NXT, STP, D0, D1, D2, D3, D4, D5, D6, D7
CAN: RxD, TxD
MDI_ETH: MDC, MDIO
2Uarts: IN2, IN1

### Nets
US_ground: J14.1 J15.1 J16.1 J17.1 J18.1 J19.1 J20.1 J21.1 J22.1 J23.1 J24.1 R109.1 R675.1 ; port US_ground, sheet PS_Config/B503_Ground  [project net B503_Ground]
3V3_RAIL: port 3V3_RAIL, sheet U_LED_US_1/3V3_RAIL
CAN1_RxD: R798.1 ; port CAN.RxD
CAN1_TxD: R799.1 ; port CAN.TxD
CSU: P1.2 R783.1 TP34.1 ; port CSU
CSU_Neg: P1.3 R109.2
CSU_Pos: P1.1 R106.2
eMMC_clk: R112.2 ; port eMMC_SDIO.CLK
eMMC_cmd: R111.2 ; port eMMC_SDIO.CMD
eMMC_data0: R105.2 ; port eMMC_SDIO.D0
eMMC_data1: R107.2 ; port eMMC_SDIO.D1
eMMC_data2: R108.2 ; port eMMC_SDIO.D2
eMMC_data3: R110.2 ; port eMMC_SDIO.D3
eMMC_data4: R101.2 ; port eMMC_SDIO.D4
eMMC_data5: R102.2 ; port eMMC_SDIO.D5
eMMC_data6: R103.2 ; port eMMC_SDIO.D6
eMMC_data7: R104.2 ; port eMMC_SDIO.D7
eMMC_rst: R99.1 R797.1 SP19.1 ; port eMMC_SDIO.Reset/CD
EXPANDER_RESET: J21.2 P13.2 R811.1 ; port EXPANDER_RESET, sheet U_LED_US_1/MIO_GPIO_2_72  [also labelled MIO_GPIO_2_72]
GEM3_MDC: R815.1 ; port MDI_ETH.MDC
GEM3_MDIO: R816.1 ; port MDI_ETH.MDIO
I2C0Master_SCL: J12.1 R85.1 R774.1 ; port I2C0.SCL  [project net I2C0_PS.SCL]
I2C0Master_SDA: J12.2 R86.1 R775.1 ; port I2C0.SDA  [project net I2C0_PS.SDA]
I2C1Master_SCL: J13.1 R83.1 R772.1 ; port I2C1.SCL  [project net I2C1_PS.SCL]
I2C1Master_SDA: J13.2 R84.1 R773.1 ; port I2C1.SDA  [project net I2C1_PS.SDA]
MIO_0: R768.2 U1.H17(MIO0)
MIO_1: R769.2 U1.A20(MIO1)
MIO_2: R770.2 U1.B19(MIO2)
MIO_3: R771.2 U1.D19(MIO3)
MIO_4: R772.2 U1.J17(MIO4)
MIO_5: R773.2 U1.C19(MIO5)
MIO_6: R774.2 U1.D20(MIO6)
MIO_7: R775.2 U1.E19(MIO7)
MIO_8: R776.2 U1.E20(MIO8)
MIO_9: R777.2 U1.F20(MIO9)
MIO_10: R778.2 U1.F18(MIO10)
MIO_11: R779.2 U1.G18(MIO11)
MIO_12: R780.2 U1.H18(MIO12)
MIO_13: R87.1 U1.G19(MIO13)
MIO_14: R88.1 U1.E18(MIO14)
MIO_15: R89.1 U1.J19(MIO15)
MIO_16: R90.1 U1.K17(MIO16)
MIO_17: R91.2 U1.C18(MIO17)
MIO_18: R92.2 U1.K18(MIO18)
MIO_19: R93.2 U1.K16(MIO19)
MIO_20: R94.2 U1.A19(MIO20)
MIO_21: R95.1 U1.H19(MIO21)
MIO_22: R96.1 U1.F17(MIO22)
MIO_23: R781.2 U1.K19(MIO23)
MIO_24: R782.2 U1.A18(MIO24)
MIO_25: R783.2 U1.B18(MIO25)
MIO_26: R784.2 U1.B20(MIO26)
MIO_27: R785.2 U1.B21(MIO27)
MIO_28: R786.2 U1.A21(MIO28)
MIO_29: R787.2 U1.D21(MIO29)
MIO_30: R788.2 U1.C21(MIO30)
MIO_31: R789.2 U1.A22(MIO31)
MIO_32: R790.2 U1.G20(MIO32)
MIO_33: R791.2 U1.C22(MIO33)
MIO_34: R792.2 U1.B24(MIO34)
MIO_35: R793.2 U1.B23(MIO35)
MIO_36: R794.2 U1.D22(MIO36)
MIO_37: R795.2 U1.F21(MIO37)
MIO_38: R796.2 U1.C23(MIO38)
MIO_39: R101.1 U1.E22(MIO39)
MIO_40: R102.1 U1.C24(MIO40)
MIO_41: R103.1 U1.D24(MIO41)
MIO_42: R104.1 U1.E23(MIO42)
MIO_43: R797.2 U1.F22(MIO43)
MIO_44: R798.2 U1.E24(MIO44)
MIO_45: R799.2 U1.F23(MIO45)
MIO_46: R105.1 U1.K20(MIO46)
MIO_47: R107.1 U1.K21(MIO47)
MIO_48: R108.1 U1.J21(MIO48)
MIO_49: R110.1 U1.G21(MIO49)
MIO_50: R111.1 U1.J20(MIO50)
MIO_51: R112.1 U1.H21(MIO51)
MIO_52: R362.1 U1.A24(MIO52)
MIO_53: R800.2 U1.B25(MIO53)
MIO_54: R115.1 U1.A23(MIO54)
MIO_55: R801.2 U1.B26(MIO55)
MIO_56: R116.1 U1.A25(MIO56)
MIO_57: R117.1 U1.A26(MIO57)
MIO_58: R118.1 U1.A28(MIO58)
MIO_59: R119.1 U1.A27(MIO59)
MIO_60: R120.1 U1.C26(MIO60)
MIO_61: R121.1 U1.B29(MIO61)
MIO_62: R122.1 U1.B28(MIO62)
MIO_63: R802.2 U1.A29(MIO63)
MIO_64: R803.2 U1.B30(MIO64)
MIO_65: R804.2 U1.D25(MIO65)
MIO_66: R805.2 U1.C27(MIO66)
MIO_67: R806.2 U1.C28(MIO67)
MIO_68: R807.2 U1.C29(MIO68)
MIO_69: R808.2 U1.D27(MIO69)
MIO_70: R809.2 U1.D26(MIO70)
MIO_71: R810.2 U1.D30(MIO71)
MIO_72: R811.2 U1.E27(MIO72)
MIO_73: R812.2 U1.E30(MIO73)
MIO_74: R813.2 U1.E29(MIO74)
MIO_75: R814.2 U1.D29(MIO75)
MIO_76: R815.2 U1.E28(MIO76)
MIO_77: R816.2 U1.E25(MIO77)
MIO_GPIO_0_12: J15.2 R780.1 ; sheet U_LED_US_1/MIO_GPIO_0_12
MIO_GPIO_0_23: J16.2 R98.1 R781.1 ; sheet U_LED_US_1/MIO_GPIO_0_23
MIO_GPIO_1_38: J17.2 R796.1 TP36.1 ; sheet U_LED_US_1/MIO_GPIO_1_38
MIO_GPIO_2_66: J19.2 R805.1 ; sheet U_LED_US_1/MIO_GPIO_2_66
MIO_GPIO_2_70: J20.2 R809.1 ; sheet U_LED_US_1/MIO_GPIO_2_70
MIO_GPIO_2_73: J22.2 R812.1 ; sheet U_LED_US_1/MIO_GPIO_2_73
MIO_GPIO_2_74: J23.2 R813.1 ; port En_I2C1, sheet U_LED_US_1/MIO_GPIO_2_74
MIO_GPIO_2_75: J24.2 R814.1 ; port En_I2C0, sheet U_LED_US_1/MIO_GPIO_2_75
PCIe_RESET: R788.1 TP35.1 ; port PCIe_RESET
PMU_GPI: J14.7 R784.1
PMU_GPI_1: J14.6 R785.1
PMU_GPI_2: J14.5 R786.1
PMU_GPI_3: J14.4 R787.1
PMU_GPI_5: J14.2 R789.1
PMU_GPO_0: J18.7 R790.1
PMU_GPO_1: J18.6 R791.1
PMU_GPO_2: J18.5 R792.1
PMU_GPO_3: J18.4 R793.1
PMU_GPO_4: J18.3 R794.1
PMU_GPO_5: J18.2 R795.1
PS_MODE1: port PS_MODE1, sheet PS_Config/PS_MODE1
PS_POR: port PS_POR, sheet PS_Config/PS_POR
PS_Reset: port PS_Reset, sheet PS_Config/PS_Reset
PSIO_VOLTAGE_3V3: R83.2 R84.2 R85.2 R86.2 R97.2 R98.2 R99.2 R106.1 R123.2 R737.2 ; port V_PullUp, port PSIO_VOLTAGE, sheet PS_Config/Vcco_PSIO0, sheet PS_Config/Vcco_PSIO3, sheet PS_Config/Vin_3V3  [also labelled US_Vpu]  [project net ETH_VDDIO]
SPI1_CLK: J25.1 R803.1 ; port SPI_Out.CLK
SPI1_CS: J25.4 R123.1 R806.1 ; port SPI_Out.~{CS}
SPI1_MISO: J25.3 R807.1 ; port SPI_Out.MISO
SPI1_MOSI: J25.2 R808.1 ; port SPI_Out.MOSI
TTC_0: R810.1 TP42.1
TTC_3: R804.1 TP38.1
uart0_RxD: R779.1 TP32.1 ; harness uart.TxD
uart0_TxD: R778.1 TP27.1 ; harness uart.RxD
uart1_RxD: R776.1 TP31.1 ; harness uart.RxD
uart1_TxD: R777.1 TP29.1 ; harness uart.TxD
USB2_CLK: R362.2 ; port USB2.0.CLK
USB2_D0: R116.2 ; port USB2.0.D0
USB2_D1: R117.2 ; port USB2.0.D1
USB2_D2: R115.2 ; port USB2.0.D2
USB2_D3: R119.2 ; port USB2.0.D3
USB2_D4: R120.2 ; port USB2.0.D4
USB2_D5: R121.2 ; port USB2.0.D5
USB2_D6: R122.2 ; port USB2.0.D6
USB2_D7: R802.1 ; port USB2.0.D7
USB2_DIR: R800.1 ; port USB2.0.DIR
USB2_NXT: R801.1 ; port USB2.0.NXT
USB2_STP: R118.2 ; port USB2.0.STP
uSD_CD: R782.1 ; port uSD_SDIO.Reset/CD
uSD_CLK: R96.2 R97.1 ; port uSD_SDIO.CLK
uSD_CMD: R95.2 ; port uSD_SDIO.CMD
uSD_D0: R87.2 ; port uSD_SDIO.D0
uSD_D1: R88.2 ; port uSD_SDIO.D1
uSD_D2: R89.2 ; port uSD_SDIO.D2
uSD_D3: R90.2 ; port uSD_SDIO.D3
uSD_D4: R91.1 ; port uSD_SDIO.D4
uSD_D5: R92.1 ; port uSD_SDIO.D5
uSD_D6: R93.1 ; port uSD_SDIO.D6
uSD_D7: R94.1 ; port uSD_SDIO.D7
NetP13_1: P13.1 R675.2
NetP13_3: P13.3 R737.1
NetR768_1: R768.1 TP21.1
NetR769_1: R769.1 TP22.1
NetR770_1: R770.1 TP23.1
NetR771_1: R771.1 TP25.1

Not connected (* = marked no-connect by the designer): J14 3*

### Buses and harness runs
harness port JTAG_US = sheet PS_Config/JTAG_US

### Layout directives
net class uSD_Lines: MIO_13, MIO_14, MIO_15, MIO_16, MIO_17, MIO_18, MIO_19, MIO_20, MIO_21, MIO_22, MIO_24
net class USB2_Lines: MIO_52, MIO_53, MIO_54, MIO_55, MIO_56, MIO_57, MIO_58, MIO_59, MIO_60, MIO_61, MIO_62, MIO_63
net class eMMC_Lines: MIO_39, MIO_40, MIO_41, MIO_42, MIO_43, MIO_46, MIO_47, MIO_48, MIO_49, MIO_50, MIO_51
net class SPI1_Group: SPI1_CLK, SPI1_CS, SPI1_MISO, SPI1_MOSI
net class USB2_Dev: USB2_CLK, USB2_D0, USB2_D1, USB2_D2, USB2_D3, USB2_D4, USB2_D5, USB2_D6, USB2_D7, USB2_DIR, USB2_NXT, USB2_STP
net class uSD_Dev: uSD_CD, uSD_CLK, uSD_CMD, uSD_D0, uSD_D1, uSD_D2, uSD_D3, uSD_D4, uSD_D5, uSD_D6, uSD_D7
net class eMMC_Dev: eMMC_clk, eMMC_cmd, eMMC_data0, eMMC_data1, eMMC_data2, eMMC_data3, eMMC_data4, eMMC_data5, eMMC_data6, eMMC_data7, eMMC_rst
net class CAN_US_01: CAN1_RxD, CAN1_TxD
net class SPI_MAIN: SPI1_CLK, SPI1_CS, SPI1_MISO, SPI1_MOSI
net class SPI1_MIO: MIO_64, MIO_67, MIO_68, MIO_69

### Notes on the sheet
- Umawiamy się, że konwersja nazw (RX na TX i TX na RX) będzie przy US+
- UG583 (1.13) August 15, 2018 strony od 175
- 3V3
- Labels drawn without touching a wire or pin: MIO_64, MIO_67, MIO_68, MIO_69

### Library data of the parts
J12 J13 J15-J17 J19-J24 = 2 Pin: Number of Positions: 2; Contact Resistance: 20mR; Current Rating: 4A; Voltage Rating: 250V; Gender: Male; Insulation Resistance: 50GR; Approvals: UL,CSA
J14 J18 = 7 Pin: JST (JAPAN SOLDERLESS TERMINALS) - B7B-XH-A (LF)(SN) - HEADER, VERTICAL, 7WAY; Connector Type: Header,Male Pin; Number of Positions: 7; Contact Resistance: 20mR; Current Rating: 3A; Voltage Rating (AC): 250V; Insulation Resistance: 1GR; Pitch: 2.5mm; Wire/Cable Gauge: 22AWG
J25 = 4 Pin: Gender: Male; Contact Resistance: 20mR; Current Rating: 3A; Voltage Rating (AC): 250V; Connector Type: Male Pin; Number of Positions: 4; Insulation Resistance: 1GR; Wire/Cable Gauge: 22AWG; Pitch: 2.5mm
P1 P13 = Header 3: CONN HEADER VERT 3POS 2.54MM; Manufacturer: TE Connectivity; Manufacturer Part Number: 640456-3; Contact Current Rating: 5A; Number of Positions: 3; Voltage Rating (AC): 250V; Contact Resistance: 6mR; Connector Type: Connector,Pin,Plug,Header; Shrouded: No (Without); Connector System: Wire-to-Board; Plating Thickness: 3.81um; PCB Mount Retention: Without; Contact Style: Straight; Mating Connector Lock: Yes (With); Gender: Male; Circuit Application: Signal; PCB Mounting Orientation: Vertical; Contact Post Length: 3.56mm; PCB Thickness: 0.063inch; Tail Length: 0.14inch; Approvals: CSA
R83-R86 R97-R99 R123 = Resistor: Manufacturer: Panasonic; Manufacturer Part Number: ERJ-2RKF4701X; Tolerance: 1%; Temperature Coefficient: 100ppm/°C; Power Rating: 100mW; Voltage Rating: 50V
R87-R90 R95 R96 R101-R105 R107 R108 R110-R112 R115-R122 R362 = Resistor: RES SMD 30 OHM 0.5% 1/16W 0402; Manufacturer: Panasonic; Manufacturer Part Number: ERA-2AKD300X; Power Rating: 62.5mW; Temperature Coefficient: 100ppm/°C; Max Power Dissipation: 63mW
R91-R94 R675 R768-R816 = Resistor: Manufacturer 1: Yageo; Manufacturer Part Number 1: RC0402JR-070RL; Power Rating: 62.5mW; Tolerance: 5%; Voltage Rating: 50V; Max Power Dissipation: 63mW; Temperature Coefficient: 200ppm/°C
R106 R109 = Resistor: PANASONIC - ERJ-2RKF1001X - SMD Chip Resistor, 0402 [1005 Metric], 1 kohm, ERJ2R Series, 50 V, Thick Film, 100 mW; Temperature Coefficient: 100ppm/°C; Tolerance: 1%; Voltage Rating (DC): 50V; Power Rating: 100mW
R737 = Resistor: Surface Mount Thick Film Resistor, Rc Series, 10 Kohm, 62.5 Mw, - 1%, 50 V, 0402 [1005 Metric]; Manufacturer: Yageo; Manufacturer Part Number: RC0402FR-0710KL; Voltage Rating: 50V; Power Rating: 62.5mW; Temperature Coefficient: 100ppm/°C
TP21-TP23 TP25 TP27 TP29 TP31 TP32 TP34-TP36 TP38 TP42 = TestPoint: Manufacturer: Keystone Electronics; Manufacturer Part Number: 5001; Plating: Silver; Body Material: PBT,Bronze; Number of Ports: 1; Insulation: Insulated; Inside Diameter: 1.27mm; Outside Diameter: 2.54mm; Hole Diameter: 1.6mm
U1 = FBVB900: FPGA Zynq UltraScale+ Family 192150 Cells 20nm Technology 0.85V 900-Pin FCBGA Tray; Manufacturer Part Number: XCZU4CG-1FBVB900E; Manufacturer: Xilinx; Peripherals: WDT,DMA; Interface: I2C,SPI,USB,Ethernet,MMC,SDIO,SD,UART,USART,EBI/EMI; Core Architecture: ARM; RAM Size: 256KB; Frequency: 500MHz; Number of I/Os: 204

## Sheet PS_Config.SchDoc: PS_Config
size A3; Organization: Altium Limited; Address1: L3, 12a Rodborough Rd; Address2: Frenchs Forest; Address3: NSW; Address4: Australia 2086
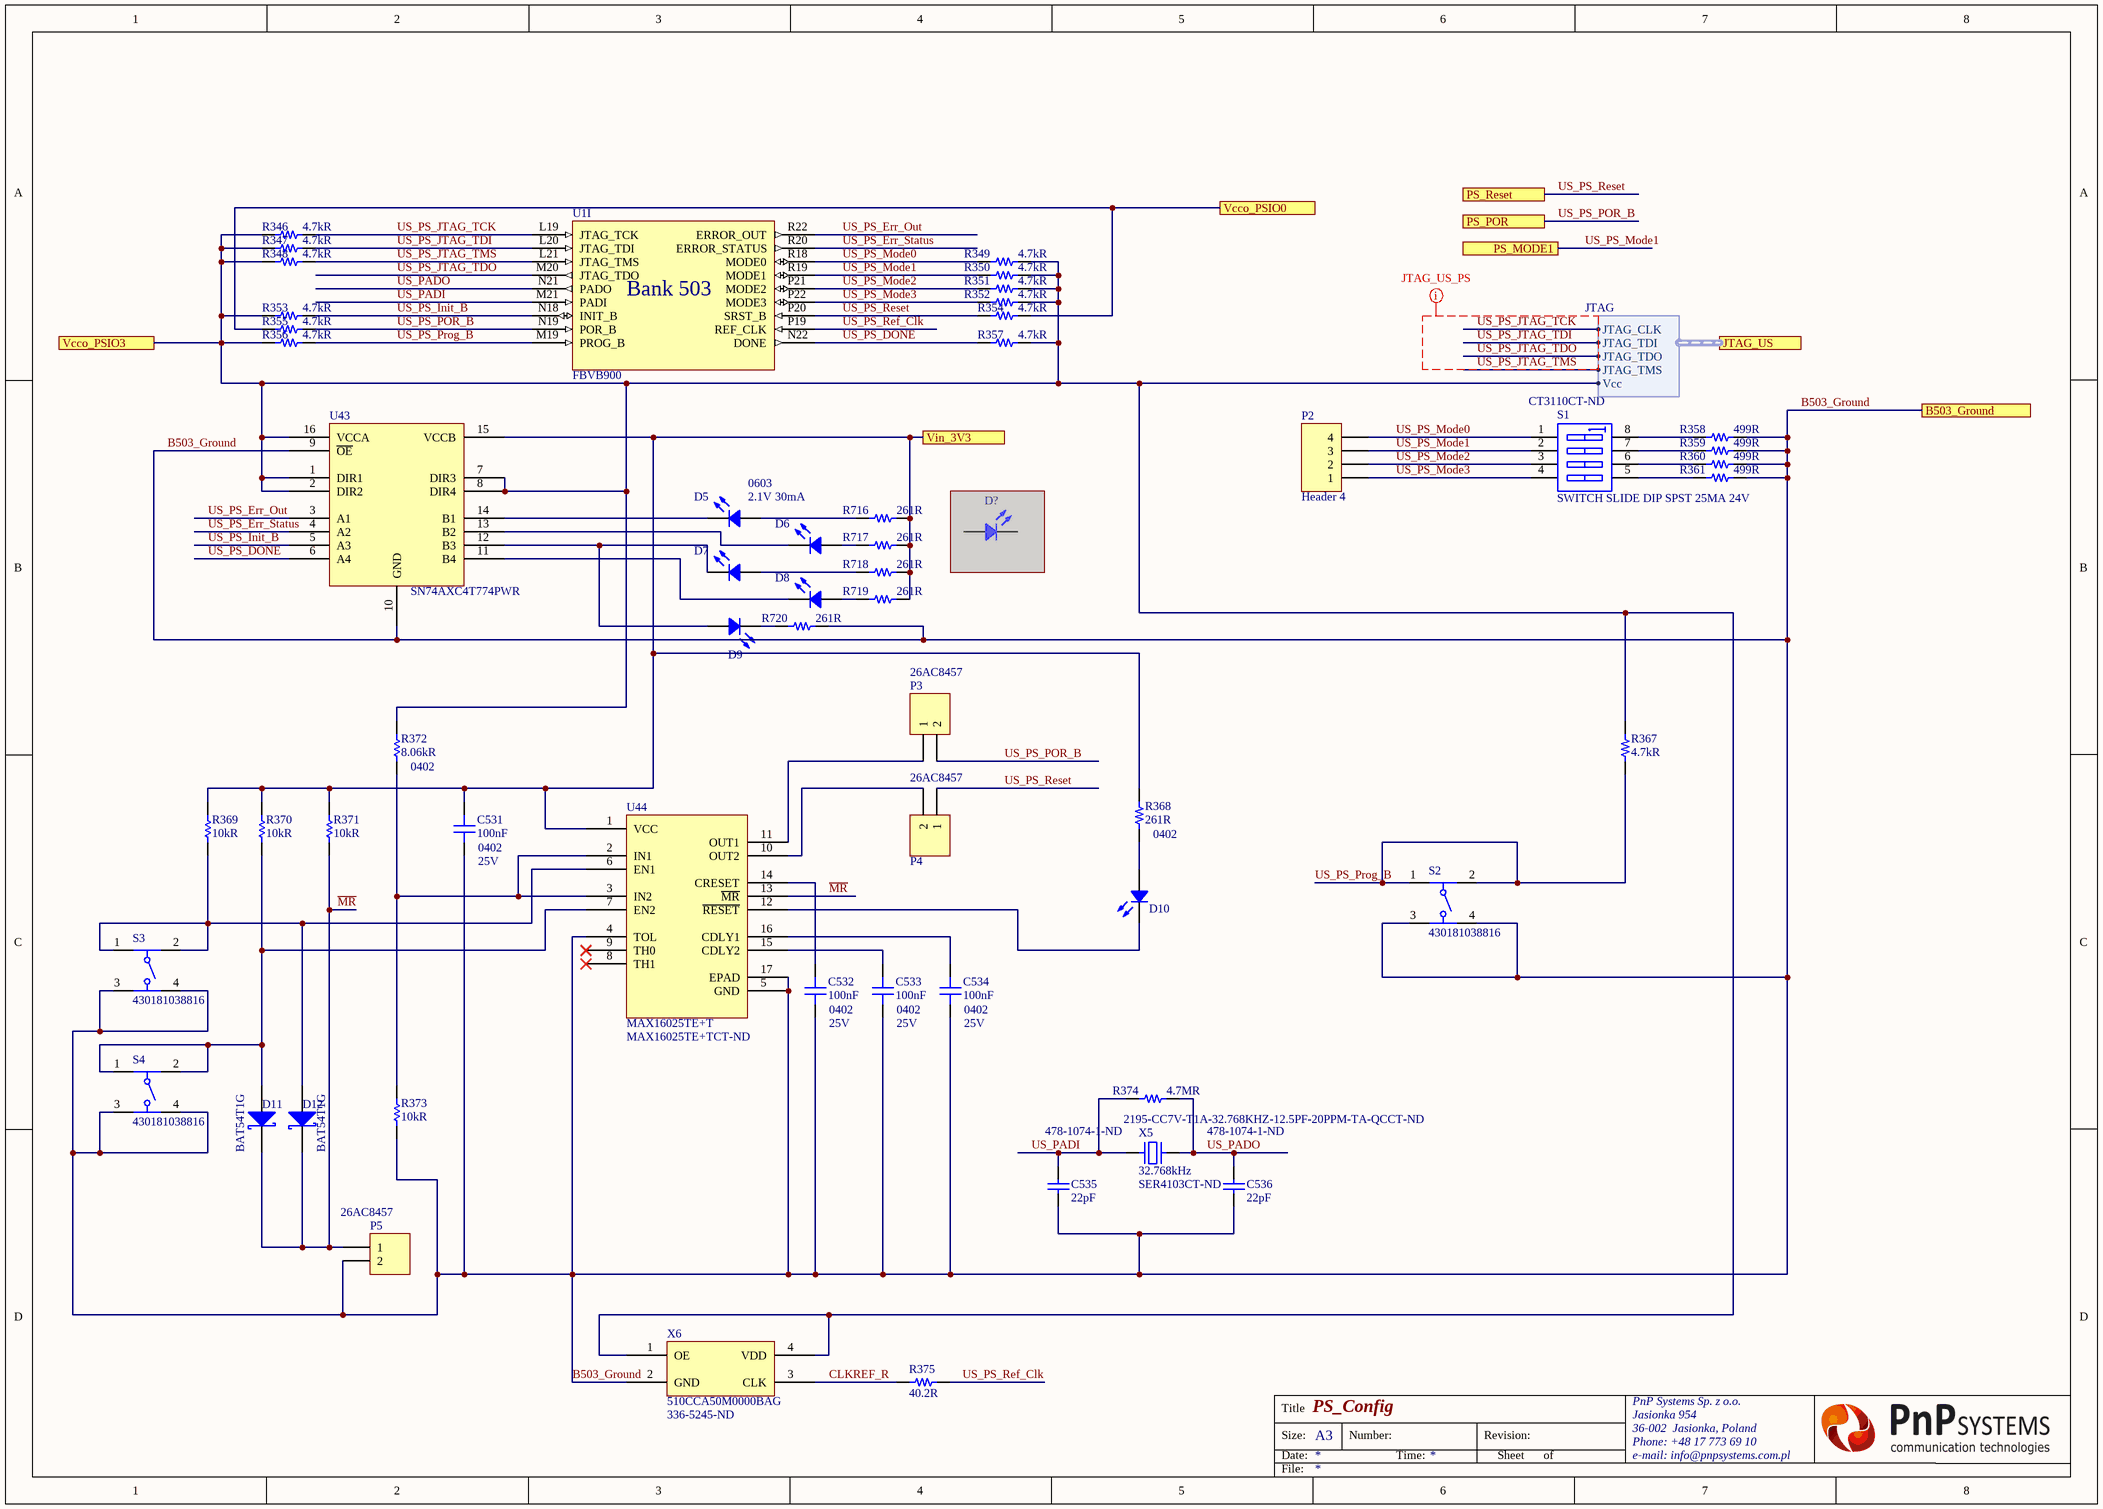
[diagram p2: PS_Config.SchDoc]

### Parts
C531  100nF  Case/Package: 0402  Voltage Rating: 25V  [CAP 0402/1005 KK]
C532  100nF  Case/Package: 0402  Voltage Rating: 25V  [CAP 0402/1005 KK]
C533  100nF  Case/Package: 0402  Voltage Rating: 25V  [CAP 0402/1005 KK]
C534  100nF  Case/Package: 0402  Voltage Rating: 25V  [CAP 0402/1005 KK]
C535  22pF  Supplier Part Number 1: 478-1074-1-ND  [CAP 0402/1005 KK]
C536  22pF  Supplier Part Number 1: 478-1074-1-ND  [CAP 0402/1005 KK]
D5  Case Code (Imperial): 0603  Forward Voltage: 2.1V  Forward Current: 30mA  [LED 0603/1608 GREEN]  (hidden comment: LTST-C190GKT)
D6  LTST-C190GKT  [LED 0603/1608 GREEN]  (value not drawn)
D7  LTST-C190GKT  [LED 0603/1608 GREEN]  (value not drawn)
D8  LTST-C190GKT  [LED 0603/1608 GREEN]  (value not drawn)
D9  LTST-C190GKT  [LED 0603/1608 GREEN]  (value not drawn)
D10  LTST-C190GKT  [LED 0603/1608 GREEN]  (value not drawn)
D11  BAT54T1G  [BAT54T1G]
D12  BAT54T1G  [BAT54T1G]
D?  LTST-C190GKT  [LED 0603/1608 GREEN]  (value not drawn)  (masked out: inside a compile mask, not in the netlist)
P2  Header 4  [HDR1X4]
P3  Supplier Part Number 1: 26AC8457  [HDR1X2]  (hidden comment: Header 2)
P4  Supplier Part Number 1: 26AC8457  [HDR1X2]  (hidden comment: Header 2)
P5  Supplier Part Number 1: 26AC8457  [HDR1X2]  (hidden comment: Header 2)
R346  4.7kR  [RES 0402/1005 RF KK]
R347  4.7kR  [RES 0402/1005 RF KK]
R348  4.7kR  [RES 0402/1005 RF KK]
R349  4.7kR  [RES 0402/1005 RF KK]
R350  4.7kR  [RES 0402/1005 RF KK]
R351  4.7kR  [RES 0402/1005 RF KK]
R352  4.7kR  [RES 0402/1005 RF KK]
R353  4.7kR  [RES 0402/1005 RF KK]
R354  4.7kR  [RES 0402/1005 RF KK]
R355  4.7kR  [RES 0402/1005 RF KK]
R356  4.7kR  [RES 0402/1005 RF KK]
R357  4.7kR  [RES 0402/1005 RF KK]
R358  499R  [RES 0402/1005 RF KK]
R359  499R  [RES 0402/1005 RF KK]
R360  499R  [RES 0402/1005 RF KK]
R361  499R  [RES 0402/1005 RF KK]
R367  4.7kR  [RES 0402/1005 RF KK]
R368  261R  Case Code (Imperial): 0402  [RES 0402/1005 RF KK]
R369  10kR  [RES 0402/1005 RF KK]
R370  10kR  [RES 0402/1005 RF KK]
R371  10kR  [RES 0402/1005 RF KK]
R372  8.06kR  Case Code (Imperial): 0402  [RES 0402/1005 RF KK]
R373  10kR  [RES 0402/1005 RF KK]
R374  4.7MR  [RES 0402/1005 RF KK]
R375  40.2R  [RES 0402/1005 RF KK]
R716  261R  [RES 0402/1005 RF KK]
R717  261R  [RES 0402/1005 RF KK]
R718  261R  [RES 0402/1005 RF KK]
R719  261R  [RES 0402/1005 RF KK]
R720  261R  [RES 0402/1005 RF KK]
S1  SWITCH SLIDE DIP SPST 25MA 24V  Supplier Part Number 1: CT3110CT-ND  [SO8_N]
S2  430181038816  [430181038816]
S3  430181038816  [430181038816]
S4  430181038816  [430181038816]
U1  FBVB900  [FBVB900 XX]  (part I of 23)
U43  SN74AXC4T774PWR  [SN74AXC4T774PWR]
U44  MAX16025TE+T  Supplier Part Number 1: MAX16025TE+TCT-ND  [MAX16025TE+T]
X5  32.768kHz  Supplier Part Number 1: SER4103CT-ND  Supplier Part Number 2: 2195-CC7V-T1A-32.768KHZ-12.5PF-20PPM-TA-QCCT-ND  [FC-135R/FC-135]
X6  510CCA50M0000BAG  Supplier Part Number 1: 336-5245-ND  [Si510]

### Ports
B503_Ground, JTAG_US (harness JTAG), PS_MODE1, PS_POR, PS_Reset, Vcco_PSIO0, Vcco_PSIO3, Vin_3V3

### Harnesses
JTAG: JTAG_CLK, JTAG_TDI, JTAG_TDO, JTAG_TMS, Vcc

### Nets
B503_Ground: C531.1 C532.1 C533.1 C534.1 C535.1 C536.1 P5.2 R358.2 R359.2 R360.2 R361.2 R373.1 R720.2 S2.3 S2.4 S3.3 S3.4 S4.3 S4.4 U43.9(~{OE}) U43.10(GND) U44.4(TOL) U44.5(GND) U44.17(EPAD) X6.2(GND) ; port B503_Ground
~{MR}: D11.1(K) D12.1(K) P5.1 R371.1 U44.13(~{MR})
CLKREF_R: R375.1 X6.3(CLK)
ETH_VDDIO: C531.2 R346.1 R347.1 R348.1 R349.2 R350.2 R351.2 R352.2 R353.1 R354.2 R355.1 R356.1 R357.2 R367.2 R368.2 R369.2 R370.2 R371.2 R372.2 R716.2 R717.2 R718.2 R719.2 U43.1(DIR1) U43.2(DIR2) U43.7(DIR3) U43.8(DIR4) U43.15(VCCB) U43.16(VCCA) U44.1(VCC) X6.1(OE) X6.4(VDD) ; port Vcco_PSIO3, port Vcco_PSIO0, port Vin_3V3, port JTAG_US.Vcc
US_PADI: C535.2 R374.1 U1.M21(PADI) X5.1
US_PADO: C536.2 R374.2 U1.N21(PADO) X5.2
US_PS_DONE: R357.1 U1.N22(DONE) U43.6(A4)
US_PS_Err_Out: U1.R22(ERROR_OUT) U43.3(A1)
US_PS_Err_Status: U1.R20(ERROR_STATUS) U43.4(A2)
US_PS_Init_B: R353.2 U1.N18(INIT_B) U43.5(A3)
US_PS_JTAG_TCK: R346.2 U1.L19(JTAG_TCK) ; port JTAG_US.JTAG_CLK
US_PS_JTAG_TDI: R347.2 U1.L20(JTAG_TDI) ; port JTAG_US.JTAG_TDI
US_PS_JTAG_TDO: U1.M20(JTAG_TDO) ; port JTAG_US.JTAG_TDO
US_PS_JTAG_TMS: R348.2 U1.L21(JTAG_TMS) ; port JTAG_US.JTAG_TMS
US_PS_Mode0: P2.4 R349.1 S1.1(A1) U1.R18(MODE0)
US_PS_Mode1: P2.3 R350.1 S1.2(A2) U1.R19(MODE1) ; port PS_MODE1  [project net PS_MODE1]
US_PS_Mode2: P2.2 R351.1 S1.3(A3) U1.P21(MODE2)
US_PS_Mode3: P2.1 R352.1 S1.4(A4) U1.P22(MODE3)
US_PS_POR_B: P3.2 R355.2 U1.N19(POR_B) ; port PS_POR  [project net PS_POR]
US_PS_Prog_B: R356.2 R367.1 S2.1 S2.2 U1.M19(PROG_B)
US_PS_Ref_Clk: R375.2 U1.P19(REF_CLK)
US_PS_Reset: P4.1 R354.1 U1.P20(SRST_B) ; port PS_Reset  [project net PS_Reset]
NetC532_2: C532.2 U44.14(CRESET)
NetC533_2: C533.2 U44.15(CDLY2)
NetC534_2: C534.2 U44.16(CDLY1)
NetD5_1: D5.1 R716.1
NetD5_2: D5.2 U43.14(B1)
NetD6_1: D6.1 R717.1
NetD6_2: D6.2 U43.13(B2)
NetD7_1: D7.1 R718.1
NetD7_2: D7.2 D9.1 U43.12(B3)
NetD8_1: D8.1 R719.1
NetD8_2: D8.2 U43.11(B4)
NetD9_2: D9.2 R720.1
NetD10_1: D10.1 R368.1
NetD10_2: D10.2 U44.12(~{RESET})
NetD11_2: D11.2(A) R370.1 S4.1 S4.2 U44.7(EN2)
NetD12_2: D12.2(A) R369.1 S3.1 S3.2 U44.6(EN1)
NetP3_1: P3.1 U44.11(OUT1)
NetP4_2: P4.2 U44.10(OUT2)
NetR358_1: R358.1 S1.8(B1)
NetR359_1: R359.1 S1.7(B2)
NetR360_1: R360.1 S1.6(B3)
NetR361_1: R361.1 S1.5(B4)
NetR372_1: R372.1 R373.2 U44.2(IN1) U44.3(IN2)

Not connected (* = marked no-connect by the designer): U44 8(TH1)* 9(TH0)*

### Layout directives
net class JTAG_US_PS: US_PS_JTAG_TCK, US_PS_JTAG_TDI, US_PS_JTAG_TDO, US_PS_JTAG_TMS

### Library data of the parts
C531-C534 = Capacitor: Manufacturer: Murata; Manufacturer Part Number: GRM155R71E104KE14J; Tolerance: 10%; Dielectric: X7R
C535 C536 = Capacitor: Manufacturer: Kyocera AVX; Manufacturer Part Number: 04025A220JAT2A; Tolerance: 5%; Voltage Rating: 50V; Dielectric: C0G; Temperature Coefficient: 30ppm/°C
D5 = LTST-C190GKT: LED,  LTST-C190GKT; Manufacturer 1: Vishay Lite-On; Color: Green; Lens Color: Colorless; Luminous Intensity: 6mcd; Viewing Angle: 130°; Lens Style: Clear,Diffused,Colorless,Rectangular; Power Rating: 100mW; Dominant Wavelength: 569nm; Test Current: 10mA; Lens Transparency: Clear; Number of Elements: 1; Wavelength: 565nm; Voltage: 2V; Reverse Voltage: 5V
D6-D10 D? = LTST-C190GKT: LED,  LTST-C190GKT; Manufacturer 1: Vishay Lite-On; Color: Green; Lens Color: Colorless; Luminous Intensity: 6mcd; Forward Voltage: 2.1V; Viewing Angle: 130°; Lens Style: Clear,Diffused,Colorless,Rectangular; Forward Current: 30mA; Power Rating: 100mW; Dominant Wavelength: 569nm; Test Current: 10mA; Lens Transparency: Clear; Number of Elements: 1; Wavelength: 565nm; Voltage: 2V; Reverse Voltage: 5V
D11 D12 = BAT54T1G: DIODE SCHOTTKY 30V 200MA SOD123; Manufacturer: ON Semiconductor; Forward Voltage: 350mV; Peak Reverse Current: 2uA; Reverse Recovery Time: 5ns; Max Forward Surge Current (Ifsm): 600mA; Element Configuration: Single; Power Dissipation: 400mW; Polarity: Standard; Capacitance: 10pF
P2 = Header 4: Header, 4-Pin
P3-P5 = Header 2: 00000005000HDR ASSY F/L SQ STR; Manufacturer: TE Connectivity; Manufacturer Part Number: 640456-2; Connector Type: Connector,Pin,Plug,Header; Shrouded: No (Without); Contact Current Rating: 5A; Connector System: Wire-to-Board; Plating Thickness: 3.81um; PCB Mount Retention: Without; Contact Resistance: 6mR; Max Voltage Rating (AC): 250V; Number of Positions: 2; Gender: Male; Contact Style: Straight; Mating Connector Lock: Yes (With); PCB Mounting Orientation: Vertical; Circuit Application: Signal; Pitch: 2.54mm; PCB Thickness: 0.063inch; Tail Length: 0.14inch; Contact Post Length: 3.56mm; Approvals: CSA
R346-R357 R367 = Resistor: as R83 on sheet Ultrascale+_01
R358-R361 = Resistor: Resistor;  Thick Film;  Res 499 Ohms;  Pwr-Rtg 0.1 W;  Tol 1%;  SMT;  0402;  Tape & Reel; Manufacturer: Panasonic; Manufacturer Part Number: ERJ-2RKF4990X; Power Rating: 100mW; Voltage Rating: 50V; Temperature Coefficient: 100ppm/°C
R368 R716-R720 = Resistor: Thick Film Resistors 0402 261ohms 1% AEC-Q200; Manufacturer: Panasonic; Manufacturer Part Number: ERJ-2RKF2610X; Power Rating: 100mW; Voltage Rating: 50V; Temperature Coefficient: 100ppm/°C
R369-R371 R373 = Resistor: Manufacturer 1: Yageo; Manufacturer Part Number 1: RC0402FR-0710KL; Tolerance: 1%; Temperature Coefficient: 100ppm/°C; Voltage Rating: 50V; Power Rating: 62.5mW
R372 = Resistor: RES 8.06K OHM 1% 1/16W 0402; Manufacturer: Stackpole Electronics; Manufacturer Part Number: RMCF0402FT8K06; Max Power Dissipation: 63mW; Temperature Coefficient: 100ppm/°C
R374 = Resistor: Thick Film Resistors 0.1W 4.7Mohms 5%; Manufacturer: KOA Speer; Manufacturer Part Number: RK73B1ETTP475J; Power Rating: 63mW; Voltage Rating: 50V; Temperature Coefficient: 200ppm/°C
R375 = Resistor: RES SMD 40.2 OHM 1% 1/16W 0402; Manufacturer: Yageo; Manufacturer Part Number: RC0402FR-0740R2L; Temperature Coefficient: 100ppm/°C; Power Rating: 62.5mW; Voltage Rating: 50V; Max Power Dissipation: 63mW
S1 = SW DIP-4: Manufacturer: CTS; Manufacturer Part Number: 218-4LPSTR; Mechanical Life: 1000Cycles; Actuator Type: Slide (Standard); Number of Positions: 4; Pitch: 0.05inch; Washable: Yes
S2-S4 = 430181038816: WS-TASV SMT Tact Switch 4.5x4.5mm, height 3.8mm, 160gf; Rated Voltage: 12VDC; Rated Current: 50mA; Washable: No
U1 = FBVB900: as U1 on sheet Ultrascale+_01
U43 = SN74AXC4T774PWR: Manufacturer 1: Texas Instruments
U44 = MAX16025TE+T: IC SUPERVISORY CIRC DL 16TQFN; Manufacturer: Maxim; Min Supply Voltage: 2.2V; Max Supply Voltage: 28V; Max Power Dissipation: 2W; Number of Voltages Monitored: 2; Reset: Active Low; Reset Timeout: 140ms; Operating Supply Current: 52uA; Watchdog Timer: No
X5 = FC-13532.7680KA-A5: CRYSTAL 32.7680 KHZ 12.5PF SMD; Manufacturer: Epson; Frequency Tolerance: 20ppm; Series Resistance: 70kR
X6 = 510CCA50M0000BAG: SMD Crystal Oscillator 50MHz 3.3V 4-Pin SMD Tray; Manufacturer: Silicon Labs; Frequency Stability: 20ppm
